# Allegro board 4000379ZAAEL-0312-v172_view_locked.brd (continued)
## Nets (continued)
GND: C1.2 C2.2 C9.2 C10.2 C11.2 C12.2 C13.2 C14.2 C15.2 C16.2 C18.2 C19.2 C20.2 C21.2 C22.2 C23.2 C24.2 C25.2 C26.2 C27.2 C28.2 C29.2 C94.2 C95.2 C96.2 C98.2 C99.2 C100.2 C101.2 C102.2 C103.2 C104.2 C105.2 C106.2 C110.2 C111.2 C112.2 C113.2 C114.2 C115.2 C116.2 C117.2 C136.2 C137.2 C139.2 C140.2 C141.2 C142.2 C143.2 C144.2 C145.2 C146.2 C148.2 C151.2 C153.2 C154.2 C155.2 C156.2 C159.2 C160.2 C161.2 C162.2 C166.1 C167.2 C168.2 C169.2 C170.1 C171.2 C172.2 C173.2 C174.2 C175.1 C176.2 C177.2 C178.2 C179.2 C180.1 C181.2 C182.1 C183.2 C184.2 C185.2 C186.2 C187.1 C188.2 C189.2 C190.2 C191.2 C192.2 C193.1 C194.2 C195.2 C196.2 C197.2 C198.2 C199.2 C200.2 C201.2 C202.2 C203.2 C204.2 C205.2 C206.2 C207.2 C208.1 C209.2 C210.2 C211.1 C212.2 C213.1 C214.1 C215.2 C216.1 C217.1 C218.2 C219.2 C220.1 C221.1 C222.2 C223.2 C224.1 C225.1 C226.2 C227.2 C228.1 C229.1 C230.2 C231.2 C232.2 C233.2 C235.2 C236.2 C238.2 C239.2 C241.2 C259.2 C260.2 C261.2 C262.2 C263.1 C264.2 C265.2 C266.2 C267.2 C272.2 C276.2 C277.2 C278.2 C279.2 C280.2 C281.2 C282.2 C283.2 C284.2 C285.2 C286.2 C293.2 C602.2 C603.2 C606.2 C607.2 C608.2 C611.2 C612.1 C613.2 C614.2 C616.2 C619.2 C620.2 C623.2 C624.2 C625.2 C626.2 C631.2 C632.2 C633.2 C634.2 C635.2 C636.2 C637.2 C638.2 C639.2 C640.2 C643.2 C644.2 C719.2 C810.2 C911.2 C922.2 C925.2 C926.2 C927.2 C928.2 C944.2 C946.2 C947.2 C948.2 C949.2 C956.2 C957.2 C958.2 C959.2 C960.2 C961.2 C971.2 C972.2 C973.2 C974.2 C976.2 C977.2 C978.2 C979.2 C980.2 C981.1 C1002.2 C1003.2 C1004.2 C1005.2 C1007.2 C1008.2 C1009.2 C1010.2 C1011.2 C1012.2 C1013.2 C1014.2 C8559.2 C8561.2 C8562.2 C8564.2 C8565.2 C8566.2 C8567.2 C8568.2 C8585.2 C8586.2 CE19.2 CE20.2 CE21.2 CE22.2 CE23.2 CE24.2 CE25.2 CE26.2 CE27.2 CE28.2 CE29.2 CE30.2 CE31.2 CE32.2 CE33.2 CE34.2 CE35.2 CE36.2 CE37.2 CE38.2 CE72.2 CE73.2 CE74.2 CE75.2 CE76.2 CE77.2 CE78.2 CE79.2 CE80.2 CE81.2 D65.1 D66.1 D67.1 D68.1 D69.1 D70.1 D71.1 D72.1 D77.1 D78.1 D87.1 D88.1 D93.1 D94.1 D95.1 D96.1 D601.C D903.2 D904.2 E1C1.2 E1C2.2 E1C14.2 E1C16.2 E1C21.2 E1C22.2 E1C23.2 E1C24.2 E1C29.2 E1C30.2 E1C31.2 E1C32.1 E1C33.2 E1C34.2 E1C35.2 E1C36.2 E1C37.1 E1C38.1 E1C39.2 E1C40.2 E1C41.2 E1C42.1 E1C43.1 E1C44.1 E1C45.2 E1C46.2 E1C47.1 E1C48.1 E1C49.1 E1C50.1 E1C51.1 E1C52.1 E1C53.1 E1C54.1 E1C55.1 E1C56.1 E1C57.1 E1C58.1 E1C59.2 E1C60.2 E1C61.1 E1C62.1 E1C63.1 E1C64.2 E1C65.1 E1C66.1 E1C67.1 E1C68.1 E1C69.1 E1C70.2 E1C71.2 E1C72.2 E1C73.2 E1C74.1 E1C75.1 E1C76.2 E1C77.1 E1C78.1 E1C79.1 E1C80.1 E1C81.2 E1C82.1 E1C83.2 E1C84.1 E1C85.1 E1C86.1 E1C87.2 E1C88.2 E1C89.1 E1C90.1 E1C91.2 E1C92.2 E1C93.2 E1C94.2 E1C95.1 E1C96.2 E1C97.2 E1C98.2 E1C99.1 E1C100.2 E1C149.2 E1C150.2 E1C151.2 E1C152.2 E1R5.1 E1R12.2 E1R13.2 E1R14.1 E1R15.1 E1R20.2 E1R26.1 E1R27.2 E1R28.2 E1R29.2 E1R30.2 E1R31.2 E1U1.4 E1U1.9 E1U1.12 E1U1.15 E1U1.18 E1U1.43 E1U1.47 E1U1.51(SGND_3) E1U1.60 E1U1.67 E1U1.69 E1U1.70 E1U1.71 E1U1.72 E1U1.73 E1U1.74 E1U1.75 E1U1.76 E1U1.77 E1U1.78 E1U1.79 E1U1.80 E1U1.81 E1U1.82 E1U1.83 E1U1.84 E1U1.85 E1U1.86 E1U1.87 E1U1.88 E1U1.89 E1U1.90 E1U1.91 E1U1.92 E1U1.93 E1U1.94 E1U1.95 E1U1.96 E1U1.97 E1U1.98 E1U1.99 E1U1.100 E1U1.101 E1U1.102 E1U1.103 E1U1.104 E1U1.105 E1U1.106 E1U1.107 E1U1.108 E1U1.109 E1U1.110 E1U1.111 E1U1.112 E1U1.113 E1U1.114 E1U1.115 E1U1.116 E1U1.117 E1U1.118 E1U1.119 E1U1.120 E1U1.121 E1U1.122 E1U1.123 E1U1.124 E1U1.125 E1U1.126 E1U1.127 E1U1.128 E1U1.129 E1U1.130 E1U1.131 E1U1.132 E1U1.133 E1U1.134 E1U1.135 E1U1.136 E1U1.137 E1U1.138 E1U1.139 E1U1.140 E1U1.141 E1U1.142 EC16.2 EC17.2 EC18.2 EC19.2 EC20.2 EC21.2 EC22.2 EC300.1 EC301.1 EC340.1 EY300.2 EY300.4(GND2) H01.1 H02.1 H03.1 H04.1 J1.5 J7.4 PC351.2 PC352.2 PC353.2 PC354.2 PC355.2 PC358.2 PC359.2 PC360.2 PC361.2 PC362.2 PC363.2 PC366.2 PC367.2 PC368.2 PC369.2 PC370.2 PC371.2 PC372.2 PC373.2 PC374.2 PC375.2 PC376.2 PC377.2 PC379.2 PC380.2 PC381.2 PC385.2 PC386.2 PC387.2 PC388.2 PC389.2 PC390.2 PC391.2 PC392.2 PC393.2 PC394.2 PC395.2 PC396.2 PC399.2 PC400.2 PC401.2 PC402.2 PC403.2 PC404.2 PC405.2 PC406.2 PC407.2 PC430.2 PC484.2 PC485.2 PC486.2 PC487.2 PC677.2 PC679.2 PC680.2 PC681.2 PC682.2 PC684.2 PC685.2 PC686.2 PC687.2 PC688.2 PC689.2 PC690.2 PR337.2 PR338.2 PR342.2 PR352.2 PR353.2 PR354.2 PR461.2 PR465.2 PR468.2 PR471.2 PR607.2 PR609.2 PU10.2 PU10.3 PU10.4 PU10.9 PU14.4 PU15.4 PU16.4 PU17.4 PU23.1 PU40.2 PU40.3 PU40.4 PU40.9 PU902.2 PU908.2 Q1.E Q2.E Q3.E Q4.E Q5.E Q6.E Q7.E Q8.E Q9.E Q10.E Q600.S(SOURCE) R28.1 R131.1 R132.1 R135.2 R136.2 R151.1 R154.2 R156.2 R174.2 R182.2 R184.2 R186.2 R188.2 R190.2 R192.2 R194.2 R199.1 R254.1 R255.1 R256.1 R257.1 R274.1 R278.2 R613.2 R621.2 R641.2 R642.1 R644.1 R647.2 R652.2 R664.2 R905.2 R916.2 R928.2 R936.2 R937.2 R939.2 R940.2 R941.2 R976.2 R978.2 R980.2 R983.2 R992.1 R993.1 R994.1 R1000.1 R1007.2 R1009.2 R1013.2 SC129.2 SC130.2 SC131.2 SC133.2 SC134.2 SC135.2 SC136.2 SC138.2 SC141.2 SC147.2 SC148.2 SC149.2 SC150.2 SC151.2 SC152.2 SC153.2 SC157.2 SC158.1 SC163.1 SC164.2 SC165.2 SC168.2 SC214.2 SC215.2 SC216.2 SC218.2 SC219.2 SC235.1 SC236.1 SC239.1 SC240.1 SC242.2 SC246.1 SC247.1 SC248.1 SC249.1 SC250.2 SC251.2 SC252.2 SC253.1 SC254.2 SC256.2 SC264.2 SC265.2 SC266.2 SC267.1 SC268.1 SC269.2 SC273.1 SC274.1 SC275.1 SC435.1 SC446.2 SC447.2 SC448.2 SC449.2 SC465.2 SC466.2 SC467.2 SC469.2 SC470.2 SC472.2 SC473.2 SC474.2 SC475.2 SC476.2 SC477.2 SC478.2 SC479.2 SC484.2 SC485.2 SC486.2 SC488.2 SC489.2 SC490.2 SC492.2 SC493.2 SC494.2 SC495.2 SC496.2 SC499.2 SC500.2 SC501.2 SC502.2 SC504.2 SC506.2 SC509.2 SC510.2 SC512.2 SC513.2 SC514.2 SC515.2 SC517.2 SC518.2 SC519.2 SC520.2 SC521.2 SC523.2 SC600.1 SC601.1 SC602.1 SF600.1 SF600.2 SF600.3 SF601.1 SF601.2 SF602.1 SF602.2 SF602.3 SF602.4 SF603.1 SF603.2 SF603.3 SF604.1 SF604.2 SF604.3 SR40.1 SR42.1 SR50.1 SR72.2 SR74.1 SR75.1 SR79.1 SR87.2 SR89.1 SR91.1 SR93.1 SR94.1 SR119.1 SR124.1 SR129.1 SR132.1 SR133.1 SR390.2 SR485.2 SR536.2 SW800.2 SW800.3 SW800.4(GND2) SY3.2 SY3.4(GND_2) T5.6 TP30.1 U1.A2 U1.A15 U1.A28 U1.AA4 U1.AA6 U1.AA10 U1.AA16 U1.AA18 U1.AB1 U1.AC6 U1.AC12 U1.AC20 U1.AC22 U1.AC25 U1.AD1 U1.AE10 U1.AE14 U1.AE16 U1.AE22 U1.AE24 U1.AF5 U1.AG1 U1.AG7 U1.AG29 U1.AH2 U1.AH11 U1.AH13 U1.AH15 U1.AH17 U1.AH21 U1.AH28 U1.B1 U1.B29 U1.C6 U1.C25 U1.D14 U1.D24 U1.E4 U1.E26 U1.F6 U1.F16 U1.F18 U1.F25 U1.H3 U1.H8 U1.H16 U1.H24 U1.H27 U1.K10 U1.K14 U1.K18 U1.K22 U1.K29 U1.M1 U1.M12 U1.M16 U1.M20 U1.M25 U1.P8 U1.P12 U1.P20 U1.P24 U1.P29 U1.R26 U1.T8 U1.T14 U1.T16 U1.T18 U1.U10 U1.U12 U1.U16 U1.U22 U1.U25 U1.U26(VSSA_XO1) U1.V1 U1.W4 U1.W8 U1.W14 U1.W18 U1.W24 U1.Y1 U5.1 U5.2 U5.3 U5.4 U7.4 U12.A9 U12.B1 U12.B3 U12.B9 U12.D1 U12.D8 U12.E1 U12.E2 U12.E8 U12.F9 U12.G1 U12.G8 U12.G9 U12.J2 U12.J8 U12.M1 U12.M9 U12.P1 U12.P9 U12.T1 U12.T9 U13.A9 U13.B1 U13.B3 U13.B9 U13.D1 U13.D8 U13.E1 U13.E2 U13.E8 U13.F9 U13.G1 U13.G8 U13.G9 U13.J2 U13.J8 U13.M1 U13.M9 U13.P1 U13.P9 U13.T1 U13.T9 U18.4 U18.9 U18.10 U18.11 U18.12 U18.13 U18.14 U18.15 U18.16 U18.17 U18.18 U18.19 U18.20 U18.21 U18.22 U18.23 U18.24 U18.25 U18.26 U18.27 U18.28 U18.29 U18.30 U18.31 U18.32 U18.33 U18.34 U18.35 U18.36 U18.37 U18.38 U18.39 U22.4 U39.3 U66.145 U108.GND U601.1 U601.12 U601.15(VSS_TX_2) U601.17 U601.30 U601.33 U601.34 U601.35 U601.36 U601.37 U601.38 U601.39 U601.40 U602.1 U602.3 U602.6 U602.8 U602.10 U602.13 U602.14 U602.15 U602.16 U602.17 U604.1 U604.2 U604.3 U604.4 U904.4 U904.8 U904.11 U904.12 U904.13 Y3.2 Y3.4(GND_2)
PGND: C255.2 C260.1 C261.1 C262.1 C263.2 C264.1 C265.1 C266.1 C267.1 C720.1 C844.2 C845.2 C846.2 C848.2 C849.2 C850.2 C851.2 C852.2 C8569.2 C8571.2 C8572.1 C8573.2 C8581.2 C8583.2 C8584.2 D812.A D817.A D818.A D819.A D820.A D821.A PU30.7 PU30.9 PU30.10 PU30.11 PU30.12 PU30.13 PU30.14 PU30.15 R499.2 R500.2 R501.2 R502.2 R1019.2 R1020.1 R1025.1 R1026.2 R1041.2 R1042.1 R1043.2 R1044.1 R1047.2 RV1.A T5.11 T5.12 U22.5 U909.7 U909.11 U909.18 U909.22 U909.23
SVDD0_CK: E1C97.1 E1C98.1 E1C99.2 E1L5.2 E1U1.50
SVDD0_TRX: E1C93.1 E1C94.1 E1C95.2 E1L6.2 E1U1.46
VCC_0V6_DDR: C143.1 C144.1 C145.1 C146.1 C976.1 C977.1 C978.1 C979.1 C980.1 R105.1 R106.1 R107.1 R108.1 R109.1 R110.1 R111.1 R112.1 R113.1 R114.1 R115.1 R116.1 R118.1 R119.1 R120.1 R121.1 R122.1 R123.1 R124.1 R125.1 R126.1 R127.1 R128.1 R130.1 R918.2 R951.1 R1036.1
VCC_0V9_PRX321: C9.1 C10.1 C11.1 C12.1 C14.1 C15.1 C167.1 C174.1 C179.1 C183.1 C208.2 C209.1 C211.2 C212.1 C214.2 C215.1 C217.2 C218.1 C221.2 C222.1 C225.2 C226.1 C229.2 C230.1 FB7.1 FB8.1 PR387.1 PR388.1 R916.1 U1.M14 U1.M18 U1.P14 U1.P16 U1.P18 U1.T12 U1.T20 U1.T22 U1.U14 U1.U18 U1.U20 U1.W12 U1.W20 U1.W22
VCC_0V9_PRX321_XFI: C2.1 C189.1 C198.1 C202.1 C206.1 C207.1 FB8.2 U1.AA24 U1.AC18 U1.T10 U1.W10
VCC_1V0_8261BE: E1C2.1 E1C29.1 E1C30.1 E1C31.1 E1C32.2 E1C33.1 E1C34.1 E1C35.1 E1C36.1 E1C37.2 E1C38.2 E1C50.2 E1C51.2 E1C52.2 E1C53.2 E1C54.2 E1C55.2 E1C56.2 E1C57.2 E1C58.2 E1C66.2 E1C67.2 E1C79.2 E1C80.2 E1C96.1 E1C100.1 E1L3.1 E1L4.1 E1L5.1 E1L6.1 E1U1.26 E1U1.32 E1U1.42 E1U1.53 E1U1.57 R937.1 RP1126.1
VCC_1V8_PRX321: C16.1 C18.1 C21.1 C22.1 C23.1 C25.1 C26.1 C27.1 C922.1 C926.1 C927.1 C1004.1 C1005.1 C1006.1 FB5.1 FB6.1 FB10.1 FB12.1 FB13.1 FB15.1 PR113.1 PU902.5(VOUT) R172.1 R928.1 R984.1
VCC_1V8_PRX321_PLL: C19.1 C20.1 C1009.1 C1010.1 C1012.1 FB14.1 PU908.5(VOUT) R980.1
VCC_1V9_8261BE: E1C23.1 E1C24.1 E1C48.2 E1C49.2 E1C68.2 E1C69.2 E1C70.1 E1C71.1 E1C72.1 E1C73.1 E1C74.2 E1C75.2 E1C84.2 E1C85.2 E1FB1.1 E1L2.1 E1LP1.1 E1R3.1 E1R24.1 E1R25.1 E1U1.24 E1U1.33 E1U1.36 E1U1.55 R939.1 RP1128.1
VCC_1V35_DDR: C94.1 C95.1 C96.1 C99.1 C100.1 C102.1 C103.1 C104.1 C105.1 C106.1 C110.1 C112.1 C113.1 C114.1 C115.1 C116.1 C140.1 C141.1 C142.1 C159.1 C168.1 C169.1 C171.1 C172.1 C176.1 C177.1 C184.1 C185.1 C190.1 C191.1 C195.1 C196.1 C200.1 C201.1 C204.1 C205.1 C232.1 C928.1 C958.1 C959.1 C960.1 C961.1 C971.1 C972.1 C973.1 C974.1 R936.1 R938.1 R1035.1 RP1124.1 U1.H6 U1.H10 U1.H12 U1.H20 U1.H22 U1.H25 U1.K8 U1.K12 U1.K16 U1.K20 U1.K24 U1.M8 U1.M24 U12.A1 U12.A8 U12.B2 U12.C1 U12.C9 U12.D2 U12.D9 U12.E9 U12.F1 U12.G7 U12.H2 U12.H9 U12.K2 U12.K8 U12.N1 U12.N9 U12.R1 U12.R9 U13.A1 U13.A8 U13.B2 U13.C1 U13.C9 U13.D2 U13.D9 U13.E9 U13.F1 U13.G7 U13.H2 U13.H9 U13.K2 U13.K8 U13.N1 U13.N9 U13.R1 U13.R9
VCC_3V3_8261BE: E1C86.2 E1C87.1 E1C88.1 E1C89.2 E1C90.2 E1C91.1 E1C92.1 E1U1.22 E1U1.31 ER331.1 RP1132.2
VCC_3V3_PON: C173.1 C178.1 C186.1 C192.1 C197.1 C199.1 C203.1 C277.1 C278.1 C616.1 C631.1 C632.1 C633.1 C634.1 C635.1 C636.1 C719.1 C911.1 C1003.1 C1008.1 CE72.1 CE73.1 CE74.1 CE75.1 CE76.1 CE77.1 CE78.1 CE79.1 CE80.1 CE81.1 D802.A D803.A D804.A D805.A D806.A D810.A D822.A D823.A D824.A D825.A FB9.1 L606.1 L607.1 L611.1 L612.1 PR383.2 PR462.2 PR464.2 PR467.2 PR470.2 PR610.2 PR612.1 PR614.1 PR619.1 PU902.1 PU908.1 R68.2 R83.2 R89.2 R93.2 R94.2 R152.1 R155.1 R181.1 R183.1 R185.1 R187.1 R191.1 R193.1 R203.1 R229.1 R230.1 R231.1 R232.1 R233.1 R234.1 R235.1 R258.1 R277.1 R350.2 R351.2 R629.2 R630.2 R809.2 R830.1 R831.1 R832.1 R833.1 R834.1 R835.1 R836.1 R837.1 R838.1 R839.1 R905.1 R949.1 R956.1 R958.1 R977.1 R979.1 R1034.1 RP1131.1 RP1132.1 U1.AA25 U1.P6 U1.U24 U1.W16 U1.W25 U18.8 U22.1 U604.8
VCC_3V3_PRX321_GPHY: C13.1 C166.2 C170.2 C175.2 C182.2 FB9.2 U1.AA20 U1.AA22 U1.AC24
VCC_3V3_PSE: C720.2 C8572.2 D3.C R91.1 R352.2 R353.2 R495.2 U22.8(VCC2) U909.1 U909.24
VCC_20V0_SYS: C17.1 C8564.1 C8565.1 C8567.1 C8585.1 C8586.1 PR386.1 PR611.1 PU23.8(VIN) R66.1 R1008.1 R1015.1 R1016.1 R1029.1 R1030.1 R1031.1 RP1123.1 RP1125.1 RP1127.1 RP1129.1 T5.3 T5.4
VCC_20V0_USB_PD: C8560.1 C8562.1 Q802.5 Q802.6 Q802.7 Q802.8 R999.1 U27.13 USB1.A4 USB1.A9 USB1.B4 USB1.B9(VBUS4)
VDD_DIG: C611.1 C625.1 C626.1 L607.2 U601.4
VDD_RX: C606.1 C623.1 C624.1 L604.1 L606.2 R605.1 U601.32
VDD_RX2: C638.1 C639.1 L605.1 L611.2
VDD_TX: C608.1 C637.1 C640.1 C643.1 C644.1 L612.2 R604.1 R606.1 R610.1 R699.1 U601.19 U601.22
1G_TCT_A: C156.1 D69.2 T2.1
1G_TCT_B: C276.1 D72.2 T2.4
1G_TCT_C: C139.1 D70.2 T2.7
1G_TCT_D: C160.1 D71.2 T2.10
1GLAN_BIDA+: P5.1 RV59.2 T2.23
1GLAN_BIDA-: P5.2 RV59.1 T2.22
1GLAN_BIDB+: P5.3 RV58.2 T2.20
1GLAN_BIDB-: P5.6 RV58.1 T2.19
1GLAN_BIDC+: P5.4 RV57.2 T2.17
1GLAN_BIDC-: P5.5 RV57.1 T2.16
1GLAN_BIDD+: P5.7 RV56.2 T2.14
1GLAN_BIDD-: P5.8 RV56.1 T2.13
1GLAN_MCT_C: C247.1 D83.1 D116.2 T2.18
1GLAN_MCT_D: C246.1 D85.1 D115.2 T2.15
2G5_TCT_A0: C280.1 D77.2 T17.1
2G5_TCT_A1: C284.1 D93.2 T17.13
2G5_TCT_B0: C282.1 D88.2 T17.4
2G5_TCT_B1: C286.1 D96.2 T17.16
2G5_TCT_C0: C279.1 D78.2 T17.7
2G5_TCT_C1: C283.1 D94.2 T17.19
2G5_TCT_D0: C281.1 D87.2 T17.10
2G5_TCT_D1: C285.1 D95.2 T17.22
2G5LAN_BIDA0+: P6.1 RV63.2 T17.47
2G5LAN_BIDA0-: P6.2 RV63.1 T17.46
2G5LAN_BIDA1+: P4.1 RV67.2 T17.35
2G5LAN_BIDA1-: P4.2 RV67.1 T17.34
2G5LAN_BIDB0+: P6.3 RV62.2 T17.44
2G5LAN_BIDB0-: P6.6 RV62.1 T17.43
2G5LAN_BIDB1+: P4.3 RV65.2 T17.32
2G5LAN_BIDB1-: P4.6 RV65.1 T17.31
2G5LAN_BIDC0+: P6.4 RV61.2 T17.41
2G5LAN_BIDC0-: P6.5 RV61.1 T17.40
2G5LAN_BIDC1+: P4.4 RV66.2 T17.29
2G5LAN_BIDC1-: P4.5 RV66.1 T17.28
2G5LAN_BIDD0+: P6.7 RV60.2 T17.38
2G5LAN_BIDD0-: P6.8 RV60.1 T17.37
2G5LAN_BIDD1+: P4.7 RV64.2 T17.26
2G5LAN_BIDD1-: P4.8 RV64.1 T17.25
2G5LAN_MCT_C0: C256.1 D105.1 D124.2 T17.42
2G5LAN_MCT_C1: C251.1 D101.1 D120.2 T17.30
2G5LAN_MCT_D0: C254.1 D107.1 D123.2 T17.39
2G5LAN_MCT_D1: C250.1 D103.1 D119.2 T17.27
10GLAN_BIDA+: P3.1 RV55.2 T1.23
10GLAN_BIDA-: P3.2 RV55.1 T1.22
10GLAN_BIDB+: P3.3 RV54.2 T1.20
10GLAN_BIDB-: P3.6 RV54.1 T1.19
10GLAN_BIDC+: P3.4 RV53.2 T1.17
10GLAN_BIDC-: P3.5 RV53.1 T1.16
10GLAN_BIDD+: P3.7 RV52.2 T1.14
10GLAN_BIDD-: P3.8 RV52.1 T1.13
10GLAN_MCT_C: C243.1 D79.1 D112.2 T1.18
10GLAN_MCT_D: C242.1 D81.1 D111.2 T1.15
10GPHY_MDI_BIDA_N: E1U1.16 RV42.1 T1.3
10GPHY_MDI_BIDA_P: E1U1.17 RV42.2 T1.2
10GPHY_MDI_BIDB_N: E1U1.11 RV41.1 T1.6
10GPHY_MDI_BIDB_P: E1U1.10 RV41.2 T1.5
10GPHY_MDI_BIDC_N: E1U1.5 RV40.1 T1.9
10GPHY_MDI_BIDC_P: E1U1.6 RV40.2 T1.8
10GPHY_MDI_BIDD_N: E1U1.3 RV39.1 T1.12(TD4-)
10GPHY_MDI_BIDD_P: E1U1.2 RV39.2 T1.11
10GPHY_TCT_A: C136.1 C137.1 C148.1 C151.1 D65.2 D66.2 D67.2 D68.2 E1C14.1 E1C16.1 E1C149.1 E1C150.1 E1C151.1 E1C152.1 E1L1.2 T1.1 T1.4 T1.7 T1.10
APD_BIAS: C612.2 R662.2 R665.2 U602.2
APD_FB: R648.2 R651.2 R664.1 U601.8
APD_PWM: Q600.G R617.1 R647.1
BS_CLK_SEL: E1R26.2 E1U1.52
BS_MDI_ORDER: E1R24.2 E1U1.35
BS_PHY_DIS: E1R25.2 E1U1.34
BS_PHYAD0: E1R27.1 E1U1.41
BS_PHYAD1: E1R28.1 E1U1.40
BS_PHYAD2: E1R29.1 E1U1.39
BS_PHYAD3: E1R30.1 E1U1.38
BS_PHYAD4: E1R31.1 E1U1.37
CC1: D128.2 R1039.2 USB1.A5
CC2: D127.2 R1040.2 USB1.B5
CLK_XTALI_50MHZ_RTL8261BE: E1R1.1 EC300.2 EY300.3
CLK_XTALO_50MHZ_RTL8261BE: E1R2.1 EC301.2 EY300.1
COMP: PU23.3 U39.4
CS+: C8558.1 R992.2 U27.7
D+: D110.2 R357.2 USB1.A6 USB1.B6
D-: D109.2 R358.2 USB1.A7 USB1.B7
DDR_A0: R105.2 U1.C23 U12.N3 U13.N3
DDR_A1: R106.2 U1.B22 U12.P7 U13.P7
DDR_A2: R107.2 U1.D22 U12.P3 U13.P3
DDR_A3: R108.2 U1.A21 U12.N2 U13.N2
DDR_A4: R109.2 U1.C21 U12.P8 U13.P8
DDR_A5: R110.2 U1.B20 U12.P2 U13.P2
DDR_A6: R111.2 U1.D20 U12.R8 U13.R8
DDR_A7: R112.2 U1.A19 U12.R2 U13.R2
DDR_A8: R113.2 U1.C19 U12.T8 U13.T8
DDR_A9: R114.2 U1.B18 U12.R3 U13.R3
DDR_A10: R115.2 U1.D18 U12.L7 U13.L7
DDR_A11: R116.2 U1.A17 U12.R7 U13.R7
DDR_A12: R118.2 U1.C17 U12.N7 U13.N7
DDR_A13: R119.2 U1.B16 U12.T3 U13.T3
DDR_A14: R120.2 U1.A11 U12.T7 U13.T7
DDR_A15: R121.2 U1.A23 U12.M7 U13.M7
DDR_ALERT: R132.2 U1.F12
DDR_BA_0: R123.2 U1.B12 U12.M2 U13.M2
DDR_BA_1: R124.2 U1.D12 U12.N8 U13.N8
DDR_BA_2/BG_0: R125.2 U1.C11 U12.M3 U13.M3
DDR_BL0_DQ0: U1.G2 U12.F2
DDR_BL0_DQ1: U1.B4 U12.F7
DDR_BL0_DQ2: U1.F3 U12.G2
DDR_BL0_DQ3: U1.A4 U12.H8
DDR_BL0_DQ4: U1.G4 U12.E3
DDR_BL0_DQ5: U1.A6 U12.F8
DDR_BL0_DQ6: U1.F1 U12.H3
DDR_BL0_DQ7: U1.D5 U12.H7
DDR_BL0_LDM: U1.C3 U12.E7
DDR_BL0_LDQS_N: U1.D2 U12.G3
DDR_BL0_LDQS_P: U1.D1 U12.F3
DDR_BL1_DQ8: U1.J2 U12.C2
DDR_BL1_DQ9: U1.N4 U12.C8
DDR_BL1_DQ10: U1.K3 U12.A3
DDR_BL1_DQ11: U1.L2 U12.D7
DDR_BL1_DQ12: U1.J4 U12.C3
DDR_BL1_DQ13: U1.P1 U12.B8
DDR_BL1_DQ14: U1.K1 U12.A2
DDR_BL1_DQ15: U1.L4 U12.A7
DDR_BL1_UDM: U1.H1 U12.D3
DDR_BL1_UDQS_N: U1.N2 U12.B7
DDR_BL1_UDQS_P: U1.M3 U12.C7
DDR_BL2_DQ16: U1.A25 U13.E3
DDR_BL2_DQ17: U1.C28 U13.F7
DDR_BL2_DQ18: U1.B26 U13.F2
DDR_BL2_DQ19: U1.F27 U13.H8
DDR_BL2_DQ20: U1.D25 U13.H3
DDR_BL2_DQ21: U1.G26 U13.F8
DDR_BL2_DQ22: U1.A26 U13.G2
DDR_BL2_DQ23: U1.F29 U13.H7
DDR_BL2_LDM: U1.G28 U13.E7
DDR_BL2_LDQS_N: U1.D29 U13.G3
DDR_BL2_LDQS_P: U1.D28 U13.F3
DDR_BL3_DQ24: U1.N28 U13.C2
DDR_BL3_DQ25: U1.J28 U13.A7
DDR_BL3_DQ26: U1.N26 U13.A3
DDR_BL3_DQ27: U1.K27 U13.B8
DDR_BL3_DQ28: U1.P27 U13.C3
DDR_BL3_DQ29: U1.J26 U13.D7
DDR_BL3_DQ30: U1.M29 U13.A2
DDR_BL3_DQ31: U1.H29 U13.C8
DDR_BL3_UDM: U1.M27 U13.D3
DDR_BL3_UDQS_N: U1.L26 U13.B7
DDR_BL3_UDQS_P: U1.L28 U13.C7
DDR_CAS_N: R127.2 U1.A13 U12.K3 U13.K3
DDR_CK_N: R133.1 U1.B14 U12.K7 U13.K7
DDR_CK_P: R133.2 U1.C15 U12.J7 U13.J7
DDR_CKE_0: R126.2 U1.B7 U12.K9 U13.K9
DDR_CS_0: R130.2 U1.B10 U12.L2 U13.L2
DDR_ODT_0: R128.2 U1.A9 U12.K1 U13.K1
DDR_PAR: R131.2 U1.F14
DDR_RAS_N: R122.2 U1.C13 U12.J3 U13.J3
DDR_RST: C24.1 U1.B24 U12.T2 U13.T2
DDR_WE_N: R951.2 U1.D16 U12.L3(\\W\E) U13.L3(\\W\E)
DDR_ZQ_0: R135.1 U12.L8
DDR_ZQ_1: R136.1 U13.L8
DUT_AVDDHC_3V3: EC16.1 EC17.1 EC18.1 EC19.1 EC20.1 EC21.1 EC22.1 J1.1(VCC) RP1131.2 SC129.1 SC130.1 SC131.1 SC138.1 SC147.1 SC149.1 SC150.1 SC157.1 SC242.1 SC264.1 SC269.1 SC448.1 SC484.1 SC485.1 SC488.1 SC489.1 SC494.1 SC495.1 SC496.1 SC504.1 SC509.1 SC510.1 SC518.1 SC519.1 SD2.C SR39.2 SR41.2 SR43.2 SR49.2 SR51.2 SR56.2 SR57.1 SR58.2 SR62.1 SR63.1 SR64.2 SR65.2 SR67.2 SR71.2 SR73.1 SR76.2 SR80.1 SR81.1 SR82.1 SR84.1 SR85.1 SR88.1 SR90.1 SR96.2 SR98.1 SR127.2 SR153.1 SR157.1 SR611.1 SR612.1 SR613.1 SR614.1 TP25.1 U5.8 U7.8 U66.7 U66.17 U66.41 U66.49 U66.61 U66.69 U66.91 U66.97 U66.106 U66.127 U66.139 U108.VCC
DUT_AVDDL_1GXG_0V95: SC218.1 SC219.1 SL17.2 U66.54
DUT_AVDDLC_0V95: R940.1 RP1130.1 SC133.1 SC148.1 SC151.1 SC152.1 SC153.1 SC214.1 SC215.1 SC216.1 SC446.1 SC447.1 SC449.1 SC465.1 SC466.1 SC467.1 SC469.1 SC470.1 SC472.1 SC473.1 SC474.1 SC475.1 SC476.1 SC477.1 SC478.1 SC479.1 SC486.1 SC490.1 SC492.1 SC493.1 SC506.1 SC512.1 SC513.1 SC514.1 SC515.1 SC517.1 SL17.1 SL29.1 U66.1 U66.2 U66.3 U66.5 U66.19 U66.21 U66.29 U66.31 U66.32 U66.39 U66.48 U66.62 U66.71 U66.78 U66.79 U66.81 U66.87 U66.89 U66.99 U66.100 U66.101 U66.105 U66.114 U66.121 U66.125 U66.126 U66.141 U66.143
DUT_SVDDLCMU_0V95: SC134.1 SC135.1 SC136.1 SC141.1 SL29.2 U66.111 U66.118
EAR_GND: C233.1 C234.2 C237.2 C238.1 C241.1 C259.1 C288.2 C293.1 C294.2 D79.2 D80.2 D81.2 D82.2 D83.2 D84.2 D85.2 D86.2 D101.2 D102.2 D103.2 D104.2 D105.2 D106.2 D107.2 D108.2 D111.1 D112.1 D113.1 D114.1 D115.1 D116.1 D117.1 D118.1 D119.1 D120.1 D121.1 D122.1 D123.1 D124.1 D125.1 D126.1 P3.G1 P3.G2 P4.G1 P4.G2 P5.G1 P5.G2 P6.G1 P6.G2
EE_M_SCL: SR64.1 SR69.1 U5.6
EE_M_SDA: SR67.1 SR70.1 U5.5
EE_SCL: R639.2 R642.2 U601.25
EE_SDA: R633.2 R644.2 U601.24
ETH1_MDC: SR138.2 U66.96
ETH1_MDIO: SR136.2 U66.98
FXM_CLKMD: R172.2 U1.R28
FXM_DDR_ZQ: R174.1 U1.F10
FXM_FSOURCE: R278.1 U1.K25
FXM_GPIO0: R155.2 R156.1 U1.V27 U18.6
FXM_GPIO1: R181.2 R182.1 U1.U28 U18.1
FXM_GPIO2: U1.V29 U18.5
FXM_GPIO3: U1.W26 U18.2
FXM_GPIO4: U1.W28 U18.3(WP#/IO2)
FXM_GPIO5: U1.Y27 U18.7
FXM_JRST_N: R83.1 R274.2 U1.U2
FXM_JTCK: R94.1 U1.F8
FXM_JTDI: R89.1 U1.U4
FXM_JTDO: R191.2 R192.1 U1.U6
FXM_JTMS: R93.1 U1.P3
FXM_P0_R: R151.2 U1.AG3
FXM_P2_TXN: C271.1 U1.AG14
FXM_P2_TXP: C270.1 U1.AF15
FXM_POR_N: C272.1 R68.1 R949.2 R963.2 R975.2 U1.K6
FXM_RCAL: R199.2 U1.AE26
FXM_XTAL1: R198.2 U1.T27
FXM_XTAL2: R197.2 U1.T29
GPIO13: R152.2 R190.1 U1.AC28
GPIO16: R183.2 R184.1 U1.AE29
GPIO30: SR175.1 U66.11
GPIO31: R185.2 R186.1 U1.T1
HRST_N: R200.2 R203.2 U1.M6
I2C_SCL: R229.2 R350.1 U1.AH19 U22.3 U27.3 U601.6
I2C_SDA: R230.2 R351.1 U1.AF19 U22.2 U27.2 U601.5
INT_PHY_N: E1U1.56 ER331.2 U1.AB29
LAS_N: L601.2 U601.20 U602.12
LAS_P: L603.2 U601.21 U602.11
LED00_STR_INI_MODE1: SC158.2 SR39.1 SR133.2 U66.12
LED09_STR_REG_IF_SEL_1: SC239.2 SR71.1 SR129.2 U66.23
LED15_STR_EN_PHY_R_FRC: SC246.2 SR79.2 SR96.1 U66.25
LED18_STR_EN_PHY: SC235.2 SR58.1 SR132.2 U66.30
LED21_STR_EN_SLV_MDC_DEG: SC253.2 SR40.2 SR41.1 U66.27
LED24_STR_POB_EN: SC236.2 SR119.2 SR127.1 U66.88
LED26_STR_EN_PLED: SC249.2 SR50.2 SR51.1 U66.84
LED27_STR_EE_MOD: SC435.2 SR56.1 SR124.2 U66.82
LED28_STR_SYS_LED_EN: SC240.2 SR74.2 SR76.1 U66.13
LED29: SC248.2 U66.10
LED_1G_1_G: CE38.1 R196.2 R838.2 SC275.2 TP15.1 U66.26
LED_1G_1_R: CE36.1 R195.1 R839.2 SC247.2 SR49.1 SR75.2 TP16.1 U66.28
LED_2G5_2_G: CE34.1 R189.2 R836.2 SC273.2 TP13.1 U66.22
LED_2G5_2_R: CE32.1 R180.1 R837.2 SC274.2 TP14.1 U66.24
LED_2G5_3_G: CE24.1 R179.2 R835.2 SC163.2 SR42.2 SR43.1 U66.16
LED_2G5_3_R: CE29.1 R178.1 R833.2 SC267.2 TP11.1 U66.18
LED_10G_4_G: CE19.1 E1U1.20 R173.2 R831.2 TP5.1
LED_10G_4_R: CE22.1 E1U1.19 R175.1 R830.2 TP4.1
LED_ETH_G: TP34.1 U1.AD29
LED_ETH_R: R193.2 R194.1 TP33.1 U1.AD27
LED_POWER_G: CE26.1 R176.1 R832.2 U1.AC26
LED_XPON_B: CE27.1 R177.1 R834.2 U1.AG28
LED_XPON_R: TP9.1 U1.Y29
MDC: E1U1.30 R235.2 SC265.1 SR69.2 SR607.2 U66.136
MDC_0: SR607.1 U1.AE7
MDIAN0: D92.2 T17.3 U66.34
MDIAN1: D100.2 T17.15 U66.45
MDIAN2: D76.2 T2.3 U66.58
MDIAP0: D92.1 T17.2 U66.33
MDIAP1: D100.1 T17.14 U66.44
MDIAP2: D76.1 T2.2 U66.57
MDIBN0: D91.2 T17.6 U66.36
MDIBN1: D99.2 T17.18 U66.47
MDIBN2: D75.2 T2.6 U66.60
MDIBP0: D91.1 T17.5 U66.35
MDIBP1: D99.1 T17.17 U66.46
MDIBP2: D75.1 T2.5 U66.59
MDICN0: D90.2 T17.9 U66.38
MDICN1: D98.2 T17.21 U66.51
MDICN2: D74.2 T2.9 U66.64
MDICP0: D90.1 T17.8 U66.37
MDICP1: D98.1 T17.20 U66.50
MDICP2: D74.1 T2.8 U66.63
MDIDN0: D89.2 T17.12 U66.42
MDIDN1: D97.2 T17.24(TD8-) U66.53
MDIDN2: D73.2 T2.12(TD4-) U66.66
MDIDP0: D89.1 T17.11 U66.40
MDIDP1: D97.1 T17.23 U66.52
MDIDP2: D73.1 T2.11 U66.65
MDIO: E1U1.29 R234.2 SC266.1 SR57.2 SR70.2 SR608.2 U66.134
MDIO_0: SR608.1 U1.W6
MPD: U601.16 U602.9
MSCL0_MSCK: SC502.1 SR603.2 SR611.2 U66.138
MSCL1_MOSI: SC501.1 SR604.2 SR612.2 U66.140
MSDA0_MISO: SC500.1 SR605.2 SR613.2 U66.142
MSDA1_MCSN: SC499.1 SR606.2 SR614.2 U66.144
OPT_RX_LOS: R233.2 R605.2 U1.AG20 U601.31
OPT_TX_SD: R277.2 U1.AE12 U601.23
OPT_TXFAULT: R232.2 R606.2 U1.AG12 U601.9
P4_LED2: SC268.2 TP12.1 U66.20
PON_RX_SLEEP: C602.1 R258.2 U1.AG18 U601.27
PON_TX_DIS: R231.2 R604.2 R613.1 U1.AE20 U601.10
PSE_54V0_P1+: C244.1 C248.1 C252.1 C257.1 C8573.1 C8574.1 C8575.1 C8576.1 C8577.1 D80.1 D84.1 D102.1 D106.1 D113.2 D117.2 D121.2 D125.2 D809.1 D811.1 D812.C(CATHODE) D813.1 D814.1 D820.C(CATHODE) R496.1 R1014.1 T1.21 T2.21 T17.33 T17.45 U909.28(VPWR)
PSE_54V0_P1-: C258.1 C8576.2 D108.1 D126.2 D813.2 F3.2 T17.48
PSE_54V0_P2-: C245.1 C8577.2 D82.1 D114.2 D814.2 D819.C(CATHODE) F4.2 T1.24
PSE_54V0_P3-: C249.1 C8574.2 D86.1 D118.2 D809.2 D821.C(CATHODE) F1.1 T2.24
PSE_54V0_P4-: C253.1 C8575.2 D104.1 D122.2 D811.2 F2.1 T17.36
PSE_SCL: R352.1 U22.6 U909.3
PSE_SDA: R353.1 U22.7 U909.4 U909.5
PTP_SYNC: SR390.1 U66.130
PWR_0V9_PLL5: C181.1 C188.1 C194.1 FB7.2 U1.AA12 U1.AA14
PWR_1V8_XFI0: C180.2 C235.1 FB10.2 U1.AC16
PWR_1V8_XFI1: C187.2 C236.1 FB6.2 U1.AA8
PWR_1V8_XFI2: C193.2 C239.1 FB5.2 U1.U8
PWR_DG: R28.2 R66.2 U1.P25
RESET#: SC168.1 SR128.1 SR143.2 U66.131
RESET_BUTTON_N: C810.1 C981.2 R809.1 R810.1 U1.T3
RESET_PHY_N: E1R22.1 U1.AB27
RESET_RTL8261BE_N: E1R3.2 E1R20.1 E1R22.2 E1U1.28 EC340.2
RESET_SUICIDE: R963.1 U1.AH6
RESETB: SC254.1 SD2.A SR88.2 SR90.2 SR143.1 U108.RST
RSET0: E1R5.2 E1U1.68
RSSI: Q603.3 R655.2 R660.1 R665.1
RSSI_IN: C603.1 R660.2 U601.26
RSV_TEST0: SR536.1 U66.80
RXIN1_N: C600.2 U602.4
RXIN1_P: C601.2 U602.5
RXIN_N: C601.1 U601.28
RXIN_P: C600.1 U601.29
RXOUT+: C610.2 U601.3
RXOUT-: C609.2 U601.2
RXOUTN: C609.1 U1.AF17
RXOUTP: C610.1 U1.AG16
S0RXN: SR259.1 U66.122
S0RXP: SR260.1 U66.123
S0TXN: SC85.1 U66.119
S0TXP: SC84.1 U66.120
SCL_M: R630.1 R639.1 U604.6
SDA_M: R629.1 R633.1 U604.5
SEL_XTAL: SR72.1 SR73.2 U66.103
SPF_CS#: SC256.1 SR142.2 TP24.1 U66.9
SPF_SCK: SC250.1 SR140.2 TP21.1 U66.4
SPF_SI: SC252.1 SR141.2 TP22.1 U66.6
SPF_SO: SC251.1 SR139.2 TP23.1 U66.8
SPI1_CS#: SR80.2 SR142.1 U7.1
SPI1_HOLD#: SC523.1 SR81.2 U7.7
SPI1_SCK: SR82.2 SR140.1 U7.6
SPI1_SI: SR85.2 SR141.1 U7.5
SPI1_SO: SR98.2 SR139.1 U7.2
SPI1_WP#: SR84.2 SR87.1 U7.3(WP#)
SWITCH_INT_N: U1.AA28 U66.132
SWITCH_RESET_N: SR63.2 SR128.2 U1.AA26
TX_BURST: R621.1 R623.1 R699.2 U1.AF13
TXIN_N: C271.2 U601.14
TXIN_P: C270.2 U601.13
U0RXD: SR159.1 U66.92
U0TXD: SR158.1 U66.90
UART0_RX: R955.2 R958.2 U1.R2
UART0_RX_1: D903.1 J7.3 R955.1
UART0_TX: R27.2 R187.2 R188.1 U1.R4
UART0_TX_1: D904.1 J7.2 R27.1
UPGND: C8557.2 C8558.2 C8560.2 C8595.2 C8596.2 D109.1 D110.1 D127.1 D128.1 R985.2 R993.2 R995.2 R996.2 R997.2 R998.2 U27.5 U27.6 U27.21 U27.22 U27.23 U27.24 U27.25 U27.26 U27.27 U27.28 U27.29 U27.30 USB1.25 USB1.26 USB1.27 USB1.28 USB1.29 USB1.30 USB1.A1 USB1.A12 USB1.B1 USB1.B12
USXGMII0_RD+: EC334.1 R611.1
USXGMII0_RD-: EC335.1 R612.1
USXGMII0_TD+: C86.1 ER359.1
USXGMII0_TD-: C87.1 ER360.1
USXGMII1_RD+: R615.1 SC84.2
USXGMII1_RD-: R616.1 SC85.2
USXGMII1_TD+: C89.1 SR260.2
USXGMII1_TD-: C93.1 SR259.2
USXGMII_RD+_RTL8261BE: E1U1.44 ER359.2
USXGMII_RD-_RTL8261BE: E1U1.45 ER360.2
USXGMII_TD+_RTL8261BE: E1U1.49 EC334.2
USXGMII_TD-_RTL8261BE: E1U1.48 EC335.2
VAA_1V8: C213.2 C216.2 C220.2 C224.2 C228.2 FB13.2 U1.H18 U1.M10 U1.M22 U1.T24
VAA_1V8_OTP: C1014.1 FB15.2 U1.AC8
VAA_1V8_PLL: C1.1 C210.1 C1013.1 FB14.2 U1.AC10 U1.AC14
VAA_1V8_PVT: C219.1 C223.1 C227.1 C231.1 FB12.2 U1.T6 U1.T25
VLD: C607.1 L600.1 R610.2 R614.1
VOUT: C8559.1 C8561.1 Q802.1 Q802.2 Q802.3(S_3) R1015.2 R1016.2 U27.15
VREFCA: C98.1 C101.1 C111.1 C117.1 C153.1 C154.1 C155.1 C948.1 C949.1 C956.1 C957.1 R918.1 R938.2 R941.1 R1037.1 U1.H14 U1.P10 U1.P22 U12.H1 U12.M8 U13.H1 U13.M8
XI: SR422.2 U66.104
XO: SR423.2 U66.102(XO)
XTAL_N_50M: E1R1.2 E1U1.66
XTAL_P_50M: E1R2.2 E1U1.65
N2858156: SC164.1 SR78.1 SR423.1 SY3.1
N2858168: SC165.1 SR78.2 SR422.1 SY3.3
N3905780: SR485.1 U66.55
N4210476: SR175.2 TP10.1
N4364334: SR603.1 TP26.1
N4425325: TP31.1 U66.85
N4425340: TP32.1 U66.83
N4758164: SR604.1 TP27.1
N4760323: SR605.1 TP28.1
N4760327: SR606.1 TP29.1
N17215587: C1002.1 PU902.3 R976.1 R977.2
N17224518: C1006.2 PU902.4 R983.1 R984.2
N17229070: C1007.1 PU908.3 R978.1 R979.2
N17229197: C1011.1 PU908.4
N17760544: C161.1 R198.1 Y3.1
N17761068: C162.1 R197.1 Y3.3
N17882333: R256.2 U1.AC4
N17882335: R254.2 U1.AD4
N17882341: R257.2 U1.AB3
N17882343: R255.2 U1.AC2
N17882349: R611.2 U1.AG4
N17882351: R612.2 U1.AH4
N17883614: R154.1 U1.AE18
N18711366: L602.1 R620.1 U601.18
N18711370: L602.2 L603.1 R620.2
N18711395: C619.1 C620.1 C621.1 D600.C R635.1 R636.1 R637.1 R638.1
N18711397: D600.A L605.2 Q600.D
N18711401: D601.A Q602.S(SOURCE) R652.1
N18711446: C621.2 R636.2 R648.1
N18711477: Q601.2 Q601.3 Q601.5 Q603.4(E2) R656.1
N18711479: Q601.6 Q603.1 R655.1
N18711481: Q601.4(E2) R638.2
N18711483: Q601.1 R637.2
N18711507: Q603.2 Q603.5 Q603.6 R656.2 R662.1
N18711644: L600.2 L601.1 R614.2
N18712169: Q602.G R651.1
N18712178: Q602.D R635.2
N18712277: R617.2 U601.7
N18712349: R623.2 U601.11
N18712445: C613.1 C614.1 L604.2 U602.7(VCC)
N18842601: CE20.1 Q1.B R173.1 R987.2
N18842628: D803.C R800.1
N18842711: CE21.1 Q2.B R175.2 R986.2
N18842733: Q2.C(3) R801.2 R986.1
N18842763: D810.C R801.1
N18842823: Q1.C(3) R800.2 R987.1
N18843479: CE28.1 Q5.B R177.2 R989.2
N18843504: D805.C R803.1
N18843506: Q5.C(3) R803.2 R989.1
N18851579: R810.2 SW800.1
N19004192: C28.1 C925.1 J7.1 R956.2
N19017731: CE30.1 Q6.B R178.2 R990.2
N19017798: D804.C R805.1
N19017800: Q6.C(3) R805.2 R990.1
N19057080: C249.2 R243.1
N19057084: C248.2 R242.1
N19057088: C247.2 R240.1
N19057092: C246.2 R239.1
N19057096: C234.1 R239.2 R240.2 R242.2 R243.2
N19110181: R200.1 TP1.1
N19140562: R641.1 U604.7(WP)
N19148827: PU23.5 R1007.1 R1008.2
N19149157: C947.1 R1036.2 U904.3 U904.5
N19149173: R1037.2 U904.6
N19149206: C944.1 R1034.2 U904.7 U904.9(S5) U904.10
N19149209: C8566.1 PU23.6
N19149219: C946.1 R1035.2 U904.1 U904.2
N19149443: PU23.2 R1009.1
N19149619: PU23.4 R1012.1 R1013.1
N19149820: C8568.1 PU23.9
N19149890: D807.C PU23.10 R1011.1
N19149964: D807.A Q803.G R1011.2
N19149982: Q803.S(SOURCE) R994.2 R1000.2 R1045.2
N19151513: CE25.1 Q4.B R176.2 R988.2
N19151587: D802.C R804.1
N19151589: Q4.C(3) R804.2 R988.1
N19164313: C255.1 D3.A R91.2 U909.2
N19164743: R1017.2 U909.8
N19164772: Q804.1 Q804.2 Q804.3 R1017.1 R1019.1 R1043.1
N19164775: F1.2 Q804.5 Q804.6 Q804.7 Q804.8 R1018.1
N19164778: R1018.2 U909.9
N19164928: Q804.4 U909.10
N19165359: Q805.1 Q805.2 Q805.3 R1020.2 R1021.1 R1044.2
N19165393: Q805.4 U909.14
N19165428: R1021.2 U909.12
N19165431: R1022.2 U909.13
N19165523: F2.2 Q805.5 Q805.6 Q805.7 Q805.8 R1022.1
N19176803: R1024.1 U909.16
N19176821: R1023.1 U909.15
N19177080: Q806.1 Q806.2 Q806.3 R1023.2 R1025.2 R1042.2
N19177140: F3.1 Q806.5 Q806.6 Q806.7 Q806.8 R1024.2
N19177464: Q806.4 U909.17
N19177597: Q807.1 Q807.2 Q807.3 R1026.1 R1027.2 R1041.1
N19177618: F4.1 Q807.5 Q807.6 Q807.7 Q807.8 R1028.2
N19177683: R1027.1 U909.19
N19177705: R1028.1 U909.20
N19177745: Q807.4 U909.21
N19198143: C847.1 C848.1 C849.1 C850.1 L65.2 R495.1 R498.1 R499.1
N19198187: C843.2 L65.1 PU30.6
N19198218: C844.1 C845.1 C846.1 PU30.8(VIN) R496.2 R497.1 RV1.C(CATHODE)
N19198237: C851.1 PU30.1 R497.2 R500.1
N19198257: C852.1 PU30.2
N19198264: PU30.3 R501.1
N19198365: C843.1 PU30.5
N19198416: C847.2 PU30.4 R498.2 R502.1
N19201777: D816.A Q803.D T5.1 T5.2
N19201879: D815.A T5.5
N19201900: D815.C R1012.2
N19202018: C17.2 D816.C R1029.2 R1030.2 R1031.2
N19202225: C8569.1 C8581.1 D808.C L912.1 R1032.2
N19202261: C8571.1 C8578.1 C8583.1 C8584.1 L912.2 Q808.C(3) R1014.2 R1033.1 R1046.1
N19202468: C8580.1 D808.A T5.7 T5.8
N19202480: C8580.2 R1032.1
N19203123: D817.C(CATHODE) Q808.B R1033.2
N19203481: C8578.2 D818.REF R1038.2 R1046.2 R1047.1
N19203514: Q808.E R1048.2
N19203544: R1048.1 R1049.1 U39.1
N19203613: C8582.1 D818.C R1049.2 U39.2
N19203897: C8582.2 R1038.1
N19489360: C86.2 U1.AE1
N19489361: C87.2 U1.AE2
N19489794: R615.2 U1.Y3
N19489796: R616.2 U1.AA2
N19489842: C89.2 U1.V3
N19489844: C93.2 U1.W2
N19492059: PC386.1 PC387.1 PC388.1 PC401.1 PC402.1 PR380.1 PR386.2 PU10.1(VIN(4.5V~24V))
N19492096: PC377.1 PC379.1 PC380.1 PC381.1 PC382.1 PC403.1 PL333.2 PR351.1 PR387.2 PR388.2
N19492104: PC404.1 PU10.8
N19492532: PC382.2 PR351.2 PR353.1 PU10.10
N19492579: PC383.1 PL333.1 PU10.6
N19492605: PR355.1 PU10.7
N19492617: PC383.2 PR355.2
N19494143: PC484.1 PR113.2 PR460.2 PR461.1 PU14.6
N19494174: PC351.1 PC352.1 PC355.1 PC356.1 PC367.1 PL180.2 PR339.1 RP1124.2
N19494227: PC356.2 PR337.1 PR339.2 PR344.2
N19494229: PC360.1 PC361.1 PC362.1 PR460.1 PU14.2(VIN(4.2~24V)) RP1123.2
N19494302: PC357.1 PL180.1 PU14.3
N19494349: PR345.1 PU14.5
N19494355: PC357.2 PR345.2
N19494368: PR344.1 PU14.8
N19494464: PC359.1 PU14.7
N19496414: PC679.1 PC680.1 PC688.1 PC689.1 PC690.1 PR611.2 PR615.1 PU40.1(VIN)
N19496468: PC682.1 PU40.8
N19496479: PC677.1 PR607.1 PR615.2 PU40.11
N19496629: PC683.2 PR608.2 PR609.1 PU40.10
N19496646: PC681.1 PC683.1 PC684.1 PC685.1 PC686.1 PC687.1 PL353.2 PR608.1 PR612.2 PR614.2 PR619.2
N19496749: PC691.1 PL353.1 PU40.6
N19496764: PR613.1 PU40.7
N19496772: PC691.2 PR613.2
N19531773: C8595.1 R997.1 R1040.1 U27.11
N19531775: C8596.1 R996.1 R1039.1 U27.12
N19531789: R998.1 R999.2 U27.1
N19531805: R991.2 U27.14
N19531807: Q802.4 R991.1
N19532107: C8557.1 U27.10(VDDM)
N19561994: PC353.1 PC354.1 PC363.1 PC364.1 PC368.1 PL181.2 PR340.1 RP1126.2
N19562052: PC364.2 PR338.1 PR340.2 PR347.2
N19562054: PC370.1 PC371.1 PC372.1 PR463.1 PU15.2(VIN(4.2~24V)) RP1125.2
N19562098: PC366.1 PR464.1 PU15.1
N19562127: PC365.1 PL181.1 PU15.3
N19562174: PR346.1 PU15.5
N19562180: PC365.2 PR346.2
N19562193: PR347.1 PU15.8
N19562289: PC369.1 PU15.7
N19563922: PC373.1 PC374.1 PC375.1 PC376.1 PC378.1 PL182.2 PR341.1 RP1128.2
N19563980: PC378.2 PR341.2 PR342.1 PR349.2
N19563982: PC390.1 PC391.1 PC392.1 PR466.1 PU16.2(VIN(4.2~24V)) RP1127.2
N19564055: PC384.1 PL182.1 PU16.3
N19564102: PR348.1 PU16.5
N19564108: PC384.2 PR348.2
N19564121: PR349.1 PU16.8
N19564217: PC389.1 PU16.7
N19565593: PC393.1 PC394.1 PC395.1 PC396.1 PC397.1 PL183.2 PR343.1 RP1130.2
N19565653: PC405.1 PC406.1 PC407.1 PR469.1 PU17.2(VIN(4.2~24V)) RP1129.2
N19565684: PC397.2 PR343.2 PR354.1 PR356.2
N19565697: PC399.1 PR470.1 PU17.1
N19565726: PC398.1 PL183.1 PU17.3
N19565773: PR350.1 PU17.5
N19565779: PC398.2 PR350.2
N19565792: PR356.1 PU17.8
N19565888: PC400.1 PU17.7
N19599376: C245.2 R251.1
N19599378: C244.2 R252.1
N19599380: C243.2 R253.1
N19599382: C242.2 R261.1
N19599384: C237.1 R251.2 R252.2 R253.2 R261.2
N19664892: SR65.1 U5.7(W\C\)
N19665679: J1.2 SC520.1 SR157.2 SR158.2
N19665693: J1.3 SC521.1 SR153.2 SR159.2
N19837833: C251.2 R246.1
N19837837: C252.2 R244.1
N19837859: C253.2 R245.1
N19837869: C250.2 R241.1
N19837873: C288.1 R241.2 R244.2 R245.2 R246.2
N19838616: C258.2 R248.1
N19838620: C257.2 R247.1
N19838624: C256.2 R250.1
N19838628: C254.2 R249.1
N19838632: C294.1 R247.2 R248.2 R249.2 R250.2
N19974700: E1U1.23 TP3.1
N20037364: R357.1 U27.8
N20037385: R358.1 U27.9
N20084108: SR62.2 SR609.1 TP17.1
N20170813: C29.1 PU23.7 R1045.1
N20369270: E1C1.1 E1C21.1 E1C22.1 E1L1.1 E1L2.2
N20751065: CE23.1 Q3.B R179.1 R1001.2
N20751067: Q3.C(3) R802.2 R1001.1
N20751191: D806.C R802.1
N20751626: CE33.1 Q8.B R180.2 R1003.2
N20751628: CE31.1 Q7.B R189.1 R1002.2
N20751630: Q7.C(3) R806.2 R1002.1
N20751632: Q8.C(3) R807.2 R1003.1
N20751867: D822.C R806.1
N20751906: D823.C R807.1
N20752359: CE37.1 Q10.B R195.2 R1005.2
N20752361: CE35.1 Q9.B R196.1 R1004.2
N20752363: Q9.C(3) R808.2 R1004.1
N20752365: Q10.C(3) R811.2 R1005.1
N20752600: D824.C R808.1
N20752639: D825.C R811.1
N20820874: R985.1 U27.19
N20820880: R995.1 U27.20
N20912001: SR89.2 U66.112
N20912029: SR91.2 U66.113
N20914921: SR93.2 U66.115
N20914922: SR94.2 U66.116
N24238736: E1R12.1 E1U1.58
N24238738: E1R13.1 E1U1.59
N24238740: E1R14.2 E1U1.54
N24238742: E1R15.2 E1U1.27
N24239054: E1U1.21 TP2.1
N26017682: SR610.2 U66.129
N26017689: SR609.2 U66.128
N26017934: SR610.1 TP18.1
N26023442: SR136.1 TP20.1
N26023467: SR138.1 TP19.1
N1912991617: TP8.1 U1.AE28
N1912991621: TP7.1 U1.AF21
N1912991629: TP6.1 U1.AF6

Pads without a net: E1U1 25 61 62; RV39 3 4 5 6; RV40 3 4 5 6; RV41 3 4 5 6; RV42 3 4 5 6; T5 9 10; U1 AF9 AF11 AF23 AG10 AG22 AG24 AG25 AG26 AH9 AH23 AH25 AH26 C9 D7 D10 F20 F22 F24; U12 J1 J9 L1 L9; U13 J1 J9 L1 L9; U27 4 16 17 18; U66 14 15 43 56 67 68 70 72 73 74 75 76 77 86 93 94 95 107 108 109 110 117 124 133 135 137; U909 6 25 26 27; USB1 A2 A3 A8 A10 A11 B2 B3 B8 B10 B11

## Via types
v1: diameter 0.457, hole 0.254, TOP to BOTTOM, 1185 vias
v2: diameter 0.559, hole 0.305, TOP to BOTTOM, 1325 vias
v3: diameter 0.406, hole 0.203, TOP to BOTTOM, 163 vias
v4: diameter 0.508, hole 0.254, TOP to BOTTOM, 173 vias

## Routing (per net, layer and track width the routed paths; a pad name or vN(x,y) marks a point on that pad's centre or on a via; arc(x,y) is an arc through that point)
0V9_PG: length 28.9
  TOP w0.254: PR383.1 136.86,65.47 133.86,65.47 133.1,64.71 130.43,64.71 v2(128.97,63.25)
  TOP w0.305: PR383.1 137.28,65.89 PU10.5
  BOTTOM w0.254: v2(128.97,63.25) 128.65,62.93 128.65,59.12 127.64,58.1 R975.1
1V9_PG: length 18
  TOP w0.305: PU16.1 69.48,73.09 69.18,72.79 PC385.1 ; PC385.1 67.13,72.79 64.83,70.48 v1(63.31,70.48) ; PC385.1 PR467.1 ; PU15.6 59.24,75.37 v1(59.25,75.37)
  BOTTOM w0.305: v1(63.31,70.48) 61.85,70.48 58.88,73.45 PR463.2
  BOTTOM w0.508: PR463.2 58.47,73.47 PR465.1 PC485.1 v1(59.25,75.37)
1V35_PG: length 51.8
  TOP w0.254: v1(131.7,71.69) 131.7,71.01 ; v1(141.48,45.78) 140.34,44.64 140.34,41.85 140.02,41.53 PR462.1 PC358.1 138.09,41.17 PU14.1
  TOP w0.305: PR352.1 134.38,70.36 135.45,70.36 135.77,70.03 PU10.11
  TOP w0.508: PR352.1 PC430.1 131.7,71.01 PR380.2
  L3 w0.254: v1(131.7,71.69) 131.7,72.96 132.21,73.47 139.57,73.47 141.48,71.56 v1(141.48,45.78)
3V3_PG: length 123.2
  TOP w0.127: v1(95.25,94.3) 96.2,95.25 97.54,95.25 98.1,94.68 PR469.2 ; PR610.1 41.93,78.41 v2(42.23,78.11) ; v1(75.59,60.61) v1(84.39,69.41) v1(89.79,74.8) ; v1(57.15,60.6) v1(48.96,60.6)
  TOP w0.254: PU17.6 99.38,91.5 98.74,92.14 PR471.1 PC487.1 PR469.2
  TOP w0.305: PR610.1 41.81,78.98 PU40.5 ; PU16.6 70.48,75.38 v1(70.42,75.44)
  L3 w0.127: v1(72.96,70.99) 74.74,69.22 84.2,69.22 v1(84.39,69.41) ; v2(42.23,78.11) 48.9,78.11 49.15,77.85 49.15,60.79 v1(48.96,60.6) ; v1(75.59,60.61) 57.15,60.61 v1(57.15,60.6) ; v1(95.25,94.3) 93.98,93.03 93.98,78.99 v1(89.79,74.8)
  BOTTOM w0.127: v1(72.96,70.99) 70.37,73.58 PR466.2
  BOTTOM w0.508: v1(70.42,75.44) 70.36,75.5 PC486.1 PR468.1 69.77,73.6 PR466.2
AVDDH_PHY0: length 4.2
  TOP w0.203: E1U1.7 v1(77,100.58) ; v1(74.32,100.59) 74.2,100.47 E1U1.14 ; E1U1.1 v1(79.4,100.56)
  TOP w0.305: E1C41.1 74.42,100.69 v1(74.32,100.59) ; v1(79.4,100.56) 79.54,100.7 E1C39.1 ; v1(77,100.58) 76.73,100.84 E1C40.1
AVDDH_PLL0: length 0.8
  TOP w0.203: E1U1.64 v1(79.35,97.49)
AVDDL_PHY0: length 1.5
  TOP w0.203: E1U1.13 v1(74.6,99.07) ; v1(76.75,99.05) 76.6,99.2 E1U1.8
AVDDL_PLL0: length 0.9
  TOP w0.203: v1(80.92,96.98) 80.82,97.09 E1U1.63
GND: length 901.6
  TOP w0.102: 106.93,54.35 106.94,54.34 106.94,54.35 ; U1.AE22 101.76,54.74 102.08,55.07 ; U1.AH11 106.51,55.59 106.63,55.47 106.63,55.06 106.94,54.75 ; 107.81,55.18 107.37,55.18 106.94,54.75 ; U1.K29 98.48,47.75 97.76,47.75 97.3,47.29 v1(97.05,47.29) ; 106.94,54.75 106.94,54.35 ; v3(105.98,41.86) 105.8,42.04 105.11,42.04 104.78,42.37 104.78,42.98 v3(104.93,43.13) ; v1(114.94,51.59) 114.52,51.59 114.3,51.37 111.67,51.37 111.54,51.24 U1.V1 ; v1(100.85,55.83) 100.9,55.89 ; 106.94,54.35 U1.AE10 ; U1.AB1 110.66,53.21 112.39,53.21 v1(112.59,53.4)
  TOP w0.127: v4(93.83,50.88) 93.05,51.66 91.85,51.66 ; 104.93,43.21 104.78,43.36 104.78,44.09 U1.A15 ; v1(123.19,43.81) 123.14,43.81 ; U1.Y1 110.42,52.1 111.02,52.1 111.25,52.32 113.31,52.32 v1(113.74,52.76) ; v4(90.68,47.43) 90.75,47.36 ; v1(105.03,57.28) 105.47,57.72 105.47,60.58 v1(105.06,60.99) ; v1(105.03,57.28) 104.81,57.06 104.81,55.61 104.78,55.59 U1.AH15 ; v1(105.03,57.28) 104.58,57.72 104.58,59.94 103.82,60.71 103.82,63.5 v1(102.93,64.39) ; 100.75,48.96 100.37,48.96 99.76,49.57 99.76,49.94 ; 91.85,51.66 91.69,51.82 89.28,51.82 v4(89.15,51.69) ; 91.85,51.66 v4(91.88,51.63) ; E1C88.2 69.47,100.06 v2(69.47,100.71) ; U13.G1 98.68,19.99 v1(98.98,19.68) ; U1.AH17 103.92,56.55 103.44,57.02 v1(103.44,57.34) 103.76,57.66 103.76,58.4 R154.2 ; 98.52,49.51 98.51,49.51 ; 98.51,49.51 U1.P29 ; 98.51,49.51 96.95,49.51 v3(96.88,49.58) ; v1(105.85,56.52) 105.65,56.31 105.65,55.59 ; v1(63.63,37.27) 63.5,37.4 62.55,37.4 62.42,37.27 62.42,36.85 U601.35 ; v4(83.69,16.64) 83.69,16.64 ; v4(86.42,13.91) 86.42,13.91 ; v1(101.35,60.2) 101.35,61.53 99.12,63.75 90.36,63.75 v1(88.77,62.17) ; v1(90.81,62.17) 91.63,62.99 98.74,62.99 100.01,61.72 v1(100.01,60.2) ; 105.65,55.59 U1.AH13 ; 105.65,55.59 105.65,55.59 ; SC512.2 126.06,91.05 ; R613.2 v1(64.45,39.1) ; v1(112.85,48.07) 112.25,48.07 111.62,48.64 110.42,48.64 U1.M1 ; U601.1 63.33,33.59 v4(63.41,33.51) ; 121.3,45.66 v1(121.35,45.66) ; 104.39,10.67 v4(104.4,10.67)
  TOP w0.152: U13.J8 91.77,21.59 91.77,21.34 92.16,20.95 92.16,20.38 91.77,19.99 ; U12.G1 117.88,19.96 119.34,19.96 v4(119.37,19.99) ; U13.J2 96.57,21.59 96.97,22 97.99,22 98.34,22.35 98.34,23.28 v1(98.61,23.54) ; U12.J8 112.14,21.59 112.53,21.98 112.53,22.76
  TOP w0.178: v1(119.4,22.85) 118.54,21.99 117.34,21.99 116.94,21.59 U12.J2 ; U601.30 61.16,31.87 v4(61.18,31.85) ; v1(98.68,27.28) 97.43,27.28 97.37,27.19 U13.T1 ; v1(119.74,25.26) 119.34,25.65 117.8,25.65 117.74,25.59 U12.P1 ; v1(98.08,55.53) U1.AG29 ; U1.H3 109.04,46.92 ; 112.53,22.76 v1(112.53,22.76) ; v3(104.93,43.13) 104.93,43.21
  TOP w0.203: v1(109.27,45.4) 109.27,45.57 U1.E4 ; v3(101.63,50.7) 101.68,50.7 102.03,51.05 U1.U22 ; U1.E4 108.75,45.81 108.23,45.29 U1.C6 ; U1.E4 108.66,46.19 U1.F6 108.53,46.41 109.04,46.92 ; U1.W24 101.21,51.96 v1(101.6,52.35) ; U12.E1 117.74,18.39 117.66,18.47 117.01,18.47 116.94,18.39 U12.E2 ; E1U1.60 80.85,95.89 v1(80.87,95.92) ; 90.96,25.59 90.97,25.59 ; 90.96,25.59 88.9,25.59 v1(88.39,26.07) ; 90.96,25.59 U13.P9 ; U1.AA16 104.89,53.11 105.7,53.11 U1.AC12 ; E1U1.47 v1(77.8,92.75) ; 90.97,19.99 91.06,19.89 91.67,19.89 91.77,19.99 U13.G8 ; U1.W14 105.7,52.3 v1(106.51,52.3) ; U1.U12 U1.U10 ; U1.H16 104.52,46.94 104.52,46.24 U1.F16 ; E1U1.43 v1(76.2,92.75) ; E1U1.67 79.58,98.69 v1(79.27,98.38) ; U1.AA4 109,52.36 v1(109,52.1) 109,51.85 U1.W4 ; 100.75,48.96 v1(100.77,48.96) 100.84,49.02 100.84,49.05 101.21,49.42 U1.P24
  TOP w0.254: U1.K14 105.28,47.83 104.98,48.13 v1(104.92,48.13) 104.92,48.19 104.49,48.63 U1.M16 ; U1.AD1 110.42,53.7 111.74,53.7 113.51,55.47 v2(114.28,55.47) ; U12.D8 112.14,17.59 v1(111.74,17.99) 112.14,18.39 U12.E8 ; U904.8 U904.11 134.47,23.69 U904.4 ; 111.33,15.19 111.34,15.19 ; 111.33,15.19 U12.A9 ; 111.33,15.19 v1(110.94,15.59) ; U1.AH28 99.01,55.9 v1(98.65,56.26) ; U12.G8 U12.G9 110.82,19.99 v1(110.79,20.02) ; 91.76,17.59 U13.D8 ; 91.76,17.59 v1(91.37,17.99) 91.77,18.39 U13.E8 ; 91.76,17.59 91.77,17.59 ; U1.F25 100.25,46.33 100.25,46.56 99.9,46.91 99.36,46.91 U1.H27 ; U1.F25 100.41,46.19 v1(100.81,46.58) 101.22,46.99 U1.H24 ; U1.F25 100.89,45.69 U1.D24 100.89,45.32 U1.C25 ; U1.F25 100.21,46.19 U1.E26 ; U1.T8 107.71,50.25 v1(107.33,49.87) 107.35,49.87 107.72,49.51 U1.P8 ; v1(98.88,43.39) 99.02,43.53 99.02,44.09 U1.A28 ; SC147.2 113.38,89.77 113.64,89.51 114.22,89.51 114.55,89.84 SC518.2 ; v1(98.61,23.54) 98.61,23.73 98.16,24.18 97.56,24.18 97.37,23.99 U13.M1 ; v1(98.55,17.13) 98.1,17.59 97.37,17.59 U13.D1 ; v1(104.91,50.62) 104.46,51.06 U1.U16 ; v1(104.91,50.62) 104.84,50.62 104.48,50.25 U1.T16 ; v1(104.91,50.62) 105.27,50.25 U1.T14 ; U12.B9 111.34,15.99 v1(110.94,16.39) ; 100.4,51.05 100.02,51.05 99.76,50.8 ; 100.4,51.05 100.4,51.05 ; 100.4,51.05 U1.U25 ; v1(103.25,52.26) 103.65,52.66 U1.AA18 ; v1(110.95,44.12) 110.94,44.13 110.87,44.13 110.42,44.58 U1.B1 ; v4(118.85,15.9) 118.76,15.99 117.74,15.99 U12.B1 ; U12.T1 117.74,27.19 118.22,27.19 118.87,26.54 v1(119.13,26.54) ; U1.AA18 U1.AC20 ; U1.AA18 U1.AA16 ; U1.AC20 102.84,53.5 ; U1.AC20 U1.AC22 ; U12.T9 111.34,27.19 110.99,27.45 v1(110.71,27.45) ; v1(104.78,45.75) 105.22,45.33 U1.D14 ; U13.P1 97.37,25.59 97.69,25.91 98.55,25.91 99.36,26.77 v1(99.68,26.77) ; v1(106.51,52.3) U1.AA10 ; U12.F9 111.33,19.19 ; 111.33,19.19 111.34,19.19 ; 111.33,19.19 110.84,19.19 v1(110.79,19.07) ; v1(110.35,56.02) U1.AH2 ; U13.B9 90.97,15.99 v1(90.57,15.59) 90.97,15.19 U13.A9 ; U1.R26 99.76,49.94 99.76,50.8 ; U12.B3 116.12,15.99 v1(115.77,16.33) ; 111.34,23.99 111.33,23.99 ; 111.33,23.99 U12.M9 ; 111.33,23.99 110.79,23.99 110.11,23.37 v1(110.11,22.76) ; v1(90.2,19.18) 90.97,19.19 U13.F9 ; v1(90.4,20.24) 90.65,19.99 U13.G9 90.96,19.99 90.97,19.99 ; U13.B1 97.37,15.99 v1(97.9,15.99) ; U1.AF5 108.56,54.52 108.2,54.17 108.2,54.03 v1(108.18,54) 108.18,53.85 U1.AC6 ; v1(119.4,22.85) 119.4,23.52 118.94,23.99 117.74,23.99 U12.M1 ; v1(109.41,25.63) 109.41,25.68 109.43,25.7 111.22,25.7 111.34,25.59 U12.P9 ; v1(110.84,55.34) 110.62,55.12 110.49,55.12 110.47,55.1 U1.AG1 110.42,55.09 ; U13.T9 90.97,27.19 90.58,27.57 v1(90.3,27.57) ; v1(104,45.84) U1.F18 ; 99.76,50.8 U1.U26 ; U1.B29 98.19,44.27 v1(98.19,44) ; U1.A2 109.92,44.09 109.92,43.62 109.96,43.59 v1(109.96,43.46) ; U12.D1 117.74,17.59 118.16,18.01 v4(118.26,18.01) 117.88,18.39 117.74,18.39 ; U13.B3 95.76,16 v1(95.37,16.39) ; 107.9,57.27 v1(107.89,57.28) ; U1.AE16 104.37,54.35 104.78,53.95 v1(104.78,53.91) 104.79,53.91 105.21,54.34 U1.AE14
  TOP w0.305: C116.2 v1(134.23,13.3) ; C8566.2 26.34,62.69 v2(26.29,62.74) ; v1(103.25,52.26) 103.27,52.26 U1.W18 ; PU40.9 37.72,78.48 v2(37.59,78.61) ; 90.97,23.99 90.96,23.99 ; 90.96,23.99 90.69,23.99 90.17,23.47 v1(90.17,22.86) ; 90.96,23.99 U13.M9 ; 100.4,44.81 100.4,44.82 ; 100.4,44.82 U1.C25 ; 100.4,44.82 100.4,44.83 ; U1.H8 v1(107.33,46.62) ; U1.W8 107.72,51.87 107.31,51.46 v1(107.31,51.44) 107.29,51.44 106.91,51.05 U1.U10 ; E1C75.1 E1C74.1 v4(72.91,91.19) ; C29.2 29.42,62.69 v2(29.46,62.74) ; U1.M20 v1(103.2,48.26) U1.K18 ; U1.D24 100.9,45.34 100.9,45.33 ; PU10.9 136.77,69.97 v2(136.91,70.1) ; U1.AE22 U1.AE24 100.62,54.35 v1(100.4,54.13) U1.AC25 ; U1.F16 104.47,46.18 104.78,45.84 v1(104.78,45.75) ; 106.91,47.8 106.91,47.81 ; 106.91,47.81 106.49,48.23 v1(106.49,48.32) ; 106.91,47.81 U1.K10 ; v1(108.67,22.78) 108.67,23.11 108.43,23.34 R135.2 ; U1.T18 103.74,50.16 104.38,50.16 U1.T16 ; C28.2 v2(138.75,56.58) ; TP30.1 v2(84.99,44.04) ; v1(98.15,18.41) 98.12,18.39 U13.E1 U13.E2
  TOP w0.381: v1(86.16,100.64) 86.16,99.82 EY300.2 86.84,99.87 v1(86.84,100.64) ; 45.19,162.08 SW800.4 ; SW800.4 46.36,163.25 ; SW800.4 44.02,163.25 ; SW800.4 45.19,164.42 ; U602.15 34.35,31.09 ; U602.15 33.22,32.22 ; U602.15 33.22,29.96 ; U602.15 32.08,31.09 ; U602.13 55.41,36.19 55.41,36.2 55.67,36.2 56.13,36.66 v4(56.13,36.77) ; 46.44,164.73 SW800.2 ; SW800.2 47.46,165.75 ; SW800.2 46.44,166.77 ; SW800.2 45.42,165.75 ; 32.08,37.69 U602.16 ; U602.16 33.22,38.82 ; U602.16 33.22,36.56 ; U602.16 34.35,37.69 ; 134.52,24.59 U904.12 ; U904.12 134.87,24.95 ; U904.12 134.87,24.24 ; SW800.3 53.36,163.25 ; SW800.3 52.19,162.08 ; SW800.3 52.19,164.42 ; SW800.3 51.02,163.25 ; J7.4 143.38,48.78 ; J7.4 143.38,46.72 ; J7.4 142.35,47.75 ; J7.4 144.41,47.75 ; EY300.4 83.74,96.32 v1(83.31,96.32) ; U602.8 52.66,33.21 ; U602.8 51.69,32.24 ; U602.8 53.62,32.24 ; J1.5 143.97,84.71 ; J1.5 142.94,83.68 ; J1.5 142.94,85.74 ; J1.5 141.91,84.71 ; SF604.1 116.72,106.4 ; SF604.1 116.72,104.93 ; SF604.1 117.76,105.67 ; SF604.1 115.68,105.67 ; 52.66,35.78 U602.14 ; U602.14 52.66,37.71 ; U602.14 53.62,36.74 ; U602.14 51.69,36.74 ; U602.10 55.66,33.79 55.95,33.5 v4(55.95,33.01) ; U602.3 55.38,28.09 55.87,28.57 v4(56.01,28.57) ; 39.58,31.09 U602.17 ; U602.17 41.85,31.09 ; U602.17 40.72,29.96 ; U602.17 40.72,32.22 ; U904.13 135.23,23.59 ; U904.13 134.87,23.24 ; U904.13 134.87,23.95 ; U904.13 134.52,23.59 ; v4(55.95,30.22) 55.68,30.49 U602.6
  TOP w0.457: 126.87,39.82 v4(126.87,36.32) v4(126.87,32.83) v4(126.87,30.54) v4(126.87,27.53) 126.94,27.47 v4(126.94,21.41) v4(126.94,19.52) v4(126.94,16.64) 126.94,15.75 v4(124.08,12.89) 121.86,10.67 v4(119.06,10.67) ; 126.87,39.82 126.87,40.08 v1(119.53,47.42) v4(118.25,48.7) ; 126.87,39.82 v1(126.88,39.82) ; v4(93.04,49.71) 93.04,49.66 88.85,45.47 v4(88.77,45.47) v4(87.12,43.81) v4(84.9,41.59) ; v4(94.36,10.67) 89.66,10.67 v4(89.64,10.69) 81.22,19.11 v4(81.22,20.32) v4(81.22,23.62) ; 99.38,10.67 v4(99.38,10.67) ; v4(110.11,10.67) 110.11,10.67
  TOP w0.508: C1011.2 v2(126.56,55) ; CE31.2 v2(55.56,16.19) ; v2(48.07,12) 48.07,12 Q6.E 48.07,13.18 SC267.1 ; v2(124.24,11.65) 125.5,12.9 C232.2 ; R182.2 v2(78.93,48.83) ; v4(89.25,47.53) 88.82,47.96 88.82,48.69 89.8,48.69 v4(90.11,48.39) ; v1(135.02,87.02) 134.18,87.02 SY3.4 134.17,86.32 v1(135.02,86.32) ; PC430.2 v2(132.78,72.58) ; C162.2 88.78,51.69 v4(89.15,51.69) ; v2(138.87,53.98) 138.88,53.98 D904.2 ; CE77.2 v2(56.58,3.62) ; SC274.1 107.25,91.88 v4(107,92.14) ; CE25.2 v1(81.47,16.26) ; CE34.2 53.66,14.49 Q7.E v2(53.66,11.87) ; SC504.2 107.6,86.71 v1(107.7,86.8) 107.81,86.91 SC129.2 ; v1(70.68,97.6) 70.87,97.41 E1C51.1 ; CE35.2 66.41,15.54 v1(66.55,15.68) ; v1(131.97,89.62) 131.52,89.17 SY3.2 ; v2(132.21,80.77) SC254.2 132.14,79.77 U108.GND ; v1(111.4,90.4) 111.44,90.36 SC150.2 ; v2(135.64,49.72) 135.53,49.62 C1003.2 ; SR72.2 119.81,85.04 SC136.2 119.66,84.49 118.26,83.08 v1(118.26,82.37) ; R192.2 v2(119.46,54.99) ; SC239.1 110.17,88.9 v1(110.3,89.03) 111.05,89.77 SC150.2 ; C973.2 v2(100.97,11.81) ; v2(35.94,13.21) 35.97,13.18 Q2.E 36.83,14.55 CE22.2 ; CE80.2 v2(76.45,3.49) ; SC150.2 SC519.2 ; CE32.2 58.87,14.49 Q8.E 58.87,12.13 v2(58.99,12) ; R156.2 77.3,48.83 v2(77.32,48.82) ; v2(128.91,53.91) 128.9,53.91 C1010.2 C1009.2 ; R186.2 v1(118.92,51.94) ; v1(106.49,60.77) 106.49,59.82 106.68,59.63 R621.2 ; SC240.1 v1(106.43,87.95) ; SC147.2 SC519.2 ; SC519.2 112.35,89.79 SC446.2 ; C1002.2 135.23,51.52 v2(135.64,51.12) ; v4(106.93,90.38) 107.39,89.92 SC268.1 SC273.1 ; D903.2 140.84,48.19 v2(140.84,48.2) ; v1(123.85,53.29) 123.83,53.31 R274.1 ; CE73.2 46.48,3.56 v2(46.42,3.49) ; CE79.2 v2(66.55,4.7) ; R978.2 v2(132.21,55.81) ; v1(77.15,15.56) 77.14,15.54 CE28.2 ; SC520.2 v2(140.69,92.31) ; PU908.2 v2(132.97,53.99) ; R190.2 94.69,55.55 v1(95.35,54.9) ; C1008.2 135.57,53.91 v2(135.64,53.98) ; C925.2 v2(139.83,57.59) ; CE21.2 v2(38.73,16.26) ; CE23.2 v2(44.01,16.26) ; C1007.2 v2(134.79,56.96) ; C1005.2 v2(126.36,50.61) ; R976.2 133.06,51.52 v2(132.92,51.38) ; v1(79.57,11.87) Q4.E 79.57,14.62 CE26.2 ; v2(30.73,13.14) 30.77,13.18 Q1.E 31.69,14.49 CE19.2 ; v4(85.22,47.31) 86.06,48.15 86.06,48.34 85.9,48.34 85.15,49.09 v4(85.03,49.09) ; CE76.2 86.8,4 v2(86.74,3.94) ; SC264.2 v2(127.13,75.95) ; v2(129.92,84.96) 129.98,85.03 SC165.2 ; SC219.2 SC218.2 118.73,96.39 SR485.2 118.73,94.14 v1(118.59,94.01) ; SR129.1 v4(106.43,88.9) ; v1(74.49,12) Q5.E 74.42,13.24 CE27.2 ; CE29.2 v2(47.12,13.72) ; C161.2 v4(90.87,49.97) ; PR352.2 v2(133.73,72.58) ; v1(69.28,12.06) 69.41,12.19 Q10.E 69.41,14.55 CE36.2 ; CE74.2 v2(56.52,4.7) ; CE75.2 v2(96.65,4) ; v1(96.27,59.75) R184.2 ; v1(95.31,59.75) R194.2 ; v2(64.2,12) Q9.E 64.2,14.43 CE38.2 ; CE72.2 v2(46.42,4.7) ; R136.2 87.77,26.07 v1(88.39,26.07) ; v2(41.21,13.21) 41.25,13.24 Q3.E 42.1,14.49 CE24.2 ; v2(33.91,16.38) 33.59,16.07 CE20.2 ; CE37.2 v1(71.31,16.13) ; SC265.2 108.19,79.11 v1(107.95,78.87) ; SR74.1 v1(110.3,87.95) ; v2(127.05,51.42) R983.2 ; CE30.2 v2(49.97,16.32) ; SC521.2 v2(140.77,89.61) ; v4(107,93.73) 107.71,93.01 SC275.1 ; R188.2 v1(118.17,50.98) ; CE81.2 v2(76.45,4.7) ; SC266.2 v1(108.71,75.82) ; CE33.2 61.29,16 v2(61.34,16) ; CE78.2 v2(66.61,3.56) ; PU902.2 v2(133.03,49.7)
  L2 w0.381: 116.72,104.93 SF604.1 ; SF604.1 117.76,105.67 ; SF604.1 116.72,106.4 ; SF604.1 115.68,105.67 ; 51.77,27.04 U602.1 ; U602.1 53.54,27.04 ; U602.1 52.66,27.93 ; U602.1 52.66,26.15 ; U904.12 135.31,24.59 ; U904.12 134.87,25.02 ; U904.12 134.44,24.59 ; U904.12 134.87,24.16 ; U904.13 135.31,23.59 ; U904.13 134.44,23.59 ; U904.13 134.87,23.16
  L3 w0.127: 111.38,62.55 115.31,62.55 v1(115.51,62.35) ; 111.38,62.55 91.88,62.55 91.12,61.79 v1(91.12,60.71) ; 111.38,62.55 v1(111.57,62.36) ; v1(66.06,75.59) 66.06,71.23 69.95,67.34 108.8,67.34 v1(109.09,67.63) ; v2(31.5,148.78) 31.75,148.53 38.04,148.53 39.43,149.92 39.43,152.97 v2(40.01,153.54) ; v1(72.9,69.15) 73.09,68.96 84.77,68.96 v1(85.03,69.22) ; v2(28.45,147.19) 29.02,147.76 38.73,147.76 v2(38.99,148.02) ; v2(29.91,146.05) 30.67,146.81 41.15,146.81 43.81,149.48 v2(44.45,149.48)
  L3 w0.254: 4.06,96.27 4.06,96.58 v2(3.84,96.81) 4.06,97.03 4.06,104.84 v2(3.84,105.06) 4.06,105.28 4.06,107.7 5.91,109.54 v2(5.91,109.92)
  L3 w0.381: U602.1 53.54,27.04 ; U602.1 52.66,27.93 ; U602.1 52.66,26.15 ; U602.1 51.77,27.04 ; SF604.1 116.72,106.4 ; SF604.1 115.68,105.67 ; SF604.1 116.72,104.93 ; SF604.1 117.76,105.67
  BOTTOM w0.102: v3(105.98,41.86) 105.98,41.92 106.43,42.37 R132.1 ; 95.4,19.63 95.25,19.63 94.74,20.14 94.74,20.24 93.19,21.79 88.7,21.79 88.52,21.97
  BOTTOM w0.127: 109.94,81.25 109.92,81.23 SC501.2 ; 104.35,41.43 104.37,41.44 105.41,41.44 105.83,41.86 v3(105.98,41.86) ; v1(109.27,96.16) 108.87,96.57 SC235.1 ; 107.06,81.23 SC500.2 ; v4(118.25,48.7) 117.55,49.4 109.8,49.4 109.29,48.89 C203.2 ; E1C65.1 72.21,99.62 v1(72.14,99.69)
  BOTTOM w0.178: 96.42,17.12 93.88,19.66 v1(93.62,19.66) ; 86.9,41.25 87.08,41.43 104.35,41.43 ; v1(110.79,20.02) 110.82,20.04 112.95,20.04 113.32,19.67 114.29,19.67 114.82,20.21 115.33,20.21
  BOTTOM w0.203: C153.2 105.54,49.52 105.85,49.22 105.85,49.09 C218.2 ; C189.2 97.45,53.02 v1(96.91,52.49) ; 96.42,17.12 96.82,17.12 96.84,17.13 ; v1(90.3,27.57) 90.3,27.68 C115.2 ; v1(104.92,48.13) 104.92,48.19
  BOTTOM w0.254: 100.28,47.68 C168.2 ; C960.2 111.32,15.2 v1(110.94,15.59) ; C103.2 119.13,26.49 v1(119.13,26.54) ; C105.2 111.74,18.45 v1(111.74,17.99) ; C102.2 110.62,27.56 110.67,27.5 v1(110.71,27.45) ; v1(114.94,51.59) 114.58,51.59 114.05,51.06 C239.2 112.44,51.06 112.07,51.43 C227.2 111.58,51.43 111.21,51.06 C193.1 110.83,50.94 C231.2 C223.2 C219.2 ; v1(110.94,16.39) 110.94,16.4 110.77,16.56 C95.2 ; v1(103.25,52.26) 103.14,52.15 C197.2 ; v1(119.74,25.26) 119.65,25.18 C104.2 ; 115.33,20.21 v1(115.33,20.2) ; C978.2 126.82,27.48 v4(126.87,27.53) ; C980.2 126.86,19.52 v4(126.94,19.52)
  BOTTOM w0.305: C205.2 98.06,16.15 v1(97.9,15.99) ; v1(95.37,16.39) 95.37,16.39 C141.2 ; v4(99.01,14.33) 98.87,14.46 C200.2 ; C956.2 88.85,22.3 88.52,21.97 ; v1(104.78,53.91) 104.89,54.03 C180.1 ; C195.2 99.18,19.49 v1(98.98,19.68) ; C111.2 99.26,20.2 99.26,19.96 v1(98.98,19.68) ; C98.2 109.81,22.75 110.1,22.75 v1(110.11,22.76) ; C142.2 115.15,16.93 ; v4(118.85,15.9) 119.41,16.47 C958.2 ; 90.07,20.57 v1(90.4,20.24) 90.83,19.81 C106.2 ; C100.2 95.86,46.91 v1(96.24,47.29) ; C959.2 97.89,20.24 98.45,19.68 v1(98.98,19.68) ; C634.2 v1(126.81,72.26) ; v4(119.98,15.26) 119.98,15.27 C94.2 ; v1(99.48,25.23) 99.47,25.25 C113.2 ; C159.2 99.61,26.71 v1(99.68,26.77) ; C110.2 C112.2 91.43,17.92 v1(91.37,17.99) ; v4(115.57,18.97) 115.62,19.02 115.62,19.05 C99.2 ; v1(109.18,18.31) 109.18,18.41 v1(110.79,20.02) ; v4(84.9,41.59) v4(82.55,39.24) 81.28,37.97 v4(81.28,34.42) 81.22,34.35 v4(81.22,30.61) v4(81.22,27.56) v4(81.22,23.62) ; v1(90.57,15.59) 90.57,15.46 90.53,15.42 C961.2 ; C114.2 111.58,43.48 v1(110.95,44.12) ; v1(107.57,18.62) 107.31,18.36 v1(105.46,18.36) v1(102.39,18.36) 98.2,18.36 v1(98.15,18.41) 98.09,18.36 96.88,18.36 95.61,19.63 95.4,19.63 ; C957.2 108.51,21.18 v4(108.81,20.88) 108.88,20.81 C96.2 ; v4(124.36,35) 124.73,35 C979.2 ; v1(90.2,19.18) 91.91,19.18 C140.2 ; C24.2 102.93,31.02 v1(102.94,31.02) ; v1(104.91,50.62) 104.72,50.43 C229.1 ; v4(119.37,19.99) 119.34,20.03 C101.2
  BOTTOM w0.356: 90.07,20.57 84.26,20.57 v4(81.22,23.62) ; v4(108.81,20.88) 108.81,19.86 v1(107.57,18.62) ; v3(104.93,43.13) 104.35,42.55 85.85,42.55 v4(84.9,41.59)
  BOTTOM w0.381: 45.19,162.08 SW800.4 ; SW800.4 45.19,164.42 ; SW800.4 44.02,163.25 ; SW800.4 46.36,163.25 ; U602.15 33.22,32.73 ; U602.15 34.85,31.09 ; U602.15 31.58,31.09 ; U602.1 52.66,28.01 ; U602.1 52.66,26.08 ; U602.1 53.62,27.04 ; U602.16 33.22,39.33 ; U602.16 31.58,37.69 ; U602.16 34.85,37.69 ; U602.16 33.22,36.05 ; SW800.3 53.36,163.25 ; SW800.3 52.19,162.08 ; SW800.3 52.19,164.42 ; SW800.3 51.02,163.25 ; U602.14 52.66,37.71 ; U602.14 53.62,36.74 ; U602.14 52.66,35.78 ; 116.72,104.93 SF604.1 ; SF604.1 116.72,106.4 ; SF604.1 115.68,105.67 ; SW800.2 47.46,165.75 ; SW800.2 46.44,166.77 ; SW800.2 46.44,164.73 ; SW800.2 45.42,165.75 ; 142.35,47.75 J7.4 ; J7.4 143.38,48.78 ; J7.4 144.41,47.75 ; J7.4 143.38,46.72 ; U904.12 135.31,24.59 ; U904.12 134.44,24.59 ; U904.12 134.87,25.02 ; 39.08,31.09 U602.17 ; U602.17 40.72,32.73 ; U602.17 42.35,31.09 ; 142.94,83.68 J1.5 ; J1.5 141.91,84.71 ; J1.5 143.97,84.71 ; J1.5 142.94,85.74 ; 134.44,23.59 U904.13 ; U904.13 134.87,23.16 ; U904.13 135.31,23.59 ; 53.62,32.24 U602.8 52.66,33.21
  BOTTOM w0.432: 100.67,17.13 103.59,17.13 ; 100.67,17.13 v1(98.55,17.13) 96.84,17.13 ; 100.67,17.13 v1(100.67,17.12) ; 103.59,17.13 v1(103.59,17.12) ; 103.59,17.13 106.44,17.13 ; v1(106.44,17.12) 106.44,17.13 ; 106.44,17.13 108.01,17.13 v1(109.18,18.31)
  BOTTOM w0.483: 86.9,41.25 82.67,37.02 82.67,24.17 84.86,21.97 88.52,21.97 88.52,21.97
  BOTTOM w0.508: 107.06,81.23 107.06,80.83 v1(107.38,80.52) ; SC246.1 SR79.1 v4(106.93,90.38) ; SC501.2 v2(109.92,80.33) ; U602.17 40.72,29.25 v4(40.72,29.13) ; SC253.1 SR40.1 107.68,92.14 v4(107,92.14) ; v1(128.02,91.95) 127.84,92.12 SC236.1 SR119.1 ; v1(115.77,16.33) 115.75,16.33 115.15,16.93 C974.2 ; v4(124.36,35) 124.08,35.28 C144.2 ; v4(51.42,36.77) 51.45,36.74 U602.14 ; v1(112.85,48.07) 112.38,47.6 112.27,47.6 C272.2 ; SC240.1 v1(106.43,87.95) ; v1(110.3,89.03) 110.17,88.9 SC239.1 ; SC247.1 SR75.1 107.2,93.93 v4(107,93.73) ; U602.8 51.51,32.24 v4(51.49,32.26) ; v1(108.29,84.41) 108.23,84.48 SC250.2 107.55,84.5 SC252.2 ; U602.16 33.2,37.71 v4(31.35,37.71) ; SR74.1 v1(110.3,87.95) ; EC20.2 v2(131.19,96.65) ; SC242.2 v2(128.14,93.98) 128.02,93.98 128,93.96 SC249.1 SR50.1 ; SC248.1 v1(107.7,86.8) ; SC435.1 SR124.1 v2(128.14,95.74) ; E1C84.1 81.97,99.3 v1(81.92,99.25) ; C972.2 94.78,15.51 95.37,16.09 v1(95.37,16.39) ; SR129.1 v4(106.43,88.9) ; U602.1 v4(51.46,27.04) ; v4(105.12,19.6) C971.2 ; SR390.2 v1(112.78,76.1) ; v4(33.2,29.18) 33.22,29.19 U602.15 ; SC502.2 112.78,80.77 v1(112.97,80.58)
  vias: v1(46.8,44.45) v1(48.26,33.72) v1(48.48,24.32) v1(49.4,58.61) v1(49.4,55.12) v1(49.4,31.88) v1(49.47,51.18) v1(49.47,41.97) v1(49.66,61.15) v1(49.85,47.62) v1(50.99,61.15) v1(50.99,59.94) v1(50.99,57.34) v1(50.99,51.63) v1(50.99,43.69) v1(51.05,48.77) v1(51.47,24.96) v1(51.88,22.67) v1(52.07,54.04) v1(52.26,58.86) v1(52.32,56.52) v1(52.39,61.15) v1(54.02,23.39) v1(54.29,46.74) v1(54.93,22.68) v1(55.24,59.69) v1(55.24,56.96) v1(55.44,74.93) v1(55.37,54.36) v1(55.37,50.8) v1(55.63,77.53) v1(55.63,71.69) v1(55.82,64.45) v1(56.01,87.88) v1(56.13,31.31) v1(56.2,80.01) v1(56.2,40.01) v1(56.39,81.79) v1(56.39,81.03) v1(56.45,61.09) v1(57.09,23.11) v1(57.59,73.79) v1(57.59,73.09) v1(57.85,77.66) v1(57.85,76.9) v1(57.85,76.07) v1(57.91,48.77) v1(57.91,45.4) v1(58.04,52.45) v1(57.98,42.04) v1(58.17,86.87) v1(58.29,39.12) v1(58.86,60.01) v1(58.99,54.48) v1(59,23.04) v1(59.05,28.96) v1(59.5,50.8) v1(59.5,38.73) v1(59.56,46.8) v1(59.56,44.26) v1(59.56,41.47) v1(59.88,77.47) v1(59.94,52.77) v1(59.89,29.57) v1(60.33,74.8) v1(60.33,74.17) v1(60.33,73.53) v1(60.33,72.9) v1(60.53,30) v1(60.64,70.87) v1(60.62,22.9) v1(60.77,76.64) v1(60.77,61.09) v1(60.83,48.26) v1(60.83,45.21) v1(60.83,38.8) v1(60.9,74.8) v1(60.9,74.17) v1(60.9,73.53) v1(60.9,72.9) v1(60.9,42.55) v1(61.02,64.45) v1(61.02,51.56) v1(61.15,39.94) v1(61.28,57.21) v1(61.29,23.9) v1(61.47,69.85) v1(61.47,68.71) v1(61.47,67.63) v1(61.53,66.67) v1(61.59,77.47) v1(61.59,54.55) v1(62.61,91.44) v1(62.61,53.4) v1(62.67,50.8) v1(62.67,46.93) v1(62.67,41.4) v1(63.12,55.88) v1(63.31,59.88) v1(63.56,48.39) v1(63.56,43.37) v1(63.94,102.04) v1(64.01,52.01) v1(64.45,94.87) v1(64.45,50.8) v1(64.45,46.93) v1(64.45,41.34) v1(64.58,99.95) v1(64.64,93.6) v1(64.9,119.25) v1(64.9,54.29) v1(64.96,96.08) v1(64.96,55.69) v1(65.34,61.15) v1(65.41,115.32) v1(65.41,101.03) v1(65.66,108.2) v1(65.66,58.42) v1(65.91,34.8) v1(65.98,33.59) v1(66.1,50.42) v1(66.1,46.74) v1(66.1,42.55) v1(66.17,119.25) v1(66.23,94.11) v1(66.17,92.65) v1(66.23,90.36) v1(66.29,85.53) v1(66.42,55.82) v1(66.55,57.34) v1(66.48,54.48) v1(66.55,53.15) v1(66.93,79.57) v1(66.93,78.3) v1(66.93,77.28) v1(66.93,76.14) v1(66.93,73.79) v1(66.87,64.45) v1(66.87,60.01) v1(67.25,84.07) v1(67.44,34.86) v1(67.44,33.53) v1(67.63,100.14) v1(67.63,97.85) v1(67.69,95.69) v1(67.82,120.02) v1(67.82,118.75) v1(67.75,55.75) v1(68.14,48.58) v1(68.14,42.29) v1(68.2,45.15) v1(68.2,38.29) v1(68.26,73.79) v1(68.39,53.4) v1(68.64,55.18) v1(68.71,92.9) v1(68.83,61.15) v1(68.96,73.79) v1(69.09,77.91) v1(69.09,77.03) v1(69.09,76.2) v1(69.06,32.26) v1(69.22,120.78) v1(69.22,51.88) v1(69.41,49.97) v1(69.41,46.99) v1(69.41,43.43) v1(69.41,40.01) v1(69.41,35.75) v1(69.47,58.61) v1(69.47,54.36) v1(69.6,103.12) v1(69.72,84.14) v1(69.66,57.4) v1(70.29,59.88) v1(70.42,86.04) v1(70.48,92.14) v1(70.87,120.78) v1(70.99,77.85) v1(71.25,86.04) v1(71.31,64.45) v1(71.5,74.99) v1(71.5,74.36) v1(71.5,73.72) v1(71.5,73.09) v1(71.82,84.45) v1(71.75,61.15) v1(71.88,77.03) v1(71.95,71.06) v1(72.07,74.99) v1(72.07,74.36) v1(72.07,73.72) v1(72.07,73.09) v1(72.14,53.47) v1(72.07,52.13) v1(72.39,120.78) v1(72.39,86.04) v1(72.55,101.78) v1(72.71,77.85) v1(72.71,58.61) v1(72.77,66.61) v1(72.9,70.23) v1(73.03,68.01) v1(73.1,98.86) v1(73.1,97.97) v1(73.34,57.4) v1(73.41,86.04) v1(73.53,53.4) v1(73.6,52.2) v1(73.91,120.78) v1(73.87,101.56) v1(73.98,59.88) v1(74.49,58.61) v1(74.61,84.14) v1(74.74,64.45) v1(74.74,53.4) v1(75.06,80.71) v1(75.18,68.01) v1(75.18,61.21) v1(75.5,52.2) v1(75.56,120.78) v1(75.63,57.4) v1(76.14,86.3) v1(76.33,81.22) v1(76.58,53.4) v1(76.96,89.73) v1(77.03,58.61) v1(77.09,120.78) v1(77.09,66.61) v1(77.15,87.44) v1(77.15,86.74) v1(77.15,85.34) v1(77.22,61.09) v1(77.53,81.22) v1(78.11,59.88) v1(78.42,87.44) v1(78.42,86.68) v1(78.42,85.34) v1(78.49,89.79) v1(78.55,52.2) v1(78.56,102.79) v1(78.61,68.01) v1(78.61,64.52) v1(78.74,120.78) v1(79.12,88.84) v1(79.25,92.96) v1(79.38,87.69) v1(79.44,86.8) v1(79.38,85.34) v1(79.63,53.47) v1(79.69,81.34) v1(79.95,58.67) v1(80.06,100.51) v1(80.33,69.79) v1(80.33,64.52) v1(80.26,52.2) v1(80.39,120.78) v1(80.45,73.66) v1(80.58,90.49) v1(80.64,66.61) v1(80.58,61.59) v1(80.71,87.63) v1(80.77,86.74) v1(80.84,85.22) v1(80.77,57.47) v1(80.9,98.63) v1(81.41,79.88) v1(81.72,75.69) v1(81.72,60.2) v1(81.72,53.47) v1(81.92,120.78) v1(81.85,96.84) v1(82.04,68.01) v1(82.36,71.82) v1(82.42,66.61) v1(82.49,84.71) v1(82.55,80.96) v1(82.49,59.31) v1(82.61,90.49) v1(82.61,61.15) v1(82.71,99.22) v1(82.68,96.84) v1(82.68,86.87) v1(82.99,93.73) v1(83.06,94.74) v1(83.31,82.87) v1(83.38,91.25) v1(83.44,64.52) v1(83.44,62.1) v1(83.5,73.03) v1(83.5,60.33) v1(83.57,120.78) v1(83.69,76.71) v1(83.69,68.01) v1(84.07,87.44) v1(84.07,57.72) v1(84.14,53.02) v1(84.23,100.64) v1(84.2,70.1) v1(84.33,55.31) v1(84.56,92.16) v1(84.65,74.04) v1(85.04,100.64) v1(85.03,75.56) v1(85.09,86.8) v1(85.09,81.41) v1(85.22,120.78) v1(85.22,83.76) v1(85.22,71.18) v1(85.41,62.1) v1(85.47,92.01) v1(85.53,66.61) v1(85.92,76.58) v1(85.85,64.52) v1(85.92,61.15) v1(86.04,56.9) v1(86.13,96.07) v1(86.3,57.98) v1(86.42,72.33) v1(86.36,70.61) v1(86.36,55.31) v1(86.74,120.78) v1(86.79,96.07) v1(87.05,94.8) v1(87.05,93.96) v1(87.25,88.84) v1(87.25,85.28) v1(87.44,92.14) v1(87.44,53.02) v1(87.48,99.85) v1(87.48,99.04) v1(87.48,98.2) v1(87.48,97.49) v1(87.5,96.68) v1(87.5,57.98) v1(87.57,62.1) v1(87.57,61.15) v1(87.69,76.96) v1(87.69,56.77) v1(87.69,23.3) v1(87.82,72.07) v1(87.88,66.61) v1(88.01,73.91) v1(88.14,69.28) v1(88.07,64.58) v1(88.33,68.01) v1(88.65,120.78) v1(88.84,57.59) v1(89.03,53.01) v1(89.53,70.74) v1(89.6,73.79) v1(89.6,61.02) v1(89.66,78.68) v1(89.98,64.45) v1(90.3,120.78) v1(90.42,76.14) v1(90.87,75.06) v1(90.93,72.14) v1(91.12,66.61) v1(91.44,70.74) v1(91.5,57.09) v1(91.82,120.78) v1(91.76,80.77) v1(91.88,93.85) v1(91.88,87.38) v1(91.95,68.07) v1(92.33,99.38) v1(92.52,73.72) v1(92.71,78.42) v1(92.71,64.45) v1(92.77,77.03) v1(92.77,72.2) v1(93.09,69.28) v1(93.85,120.78) v1(93.92,110.11) v1(94.42,104.01) v1(94.49,96.52) v1(94.49,94.87) v1(94.49,75.69) v1(94.81,70.74) v1(94.93,68.07) v1(95.31,79.95) v1(95.31,66.61) v1(95.5,120.78) v1(95.69,86.04) v1(95.71,83.39) v1(96.08,77.34) v1(96.27,103.12) v1(96.27,100.33) v1(96.33,89.09) v1(96.27,88.27) v1(96.39,96.77) v1(96.65,101.22) v1(96.65,94.74) v1(96.65,93.28) v1(96.65,64.45) v1(96.8,105.77) v1(97.03,120.78) v1(97.03,72.2) v1(97.13,84.05) v1(97.09,69.34) v1(97.79,80.01) v1(97.79,78.74) v1(97.85,77.22) v1(98.07,106.43) v1(98.11,104.46) v1(98.12,85.62) v1(98.12,84.94) v1(98.17,60.2) v1(98.49,68.14) v1(98.55,110.36) v1(98.65,89.31) v1(99.24,105.71) v1(99.19,95.69) v1(99.31,120.78) v1(99.31,70.8) v1(99.82,110.36) v1(99.82,64.45) v1(99.95,104.46) v1(99.89,102.68) v1(100.08,66.61) v1(100.58,93.22) v1(100.58,92.52) v1(100.74,95.17) v1(100.97,120.78) v1(100.97,88.67) v1(101.16,103.31) v1(101.32,105.77) v1(101.28,93.22) v1(101.28,92.52) v1(101.41,72.2) v1(101.54,76.96) v1(101.54,69.41) v1(102.43,68.07) v1(102.49,120.78) v1(102.49,104.52) v1(102.49,101.98) v1(102.87,91.31) v1(102.93,66.61) v1(103.03,59.85) v1(103.31,80.14) v1(103.25,70.8) v1(103.89,103.25) v1(103.96,105.82) v1(104.52,120.78) v1(104.52,110.49) v1(104.65,112.27) v1(104.73,74.25) v1(104.71,64.58) v1(105.16,72.2) v1(105.16,66.61) v1(105.28,101.98) v1(105.6,106.43) v1(105.73,68.14) v1(105.92,112.27) v1(106.17,120.78) v1(106.3,103.25) v1(106.55,99.82) v1(106.81,66.61) v1(107.44,104.01) v1(107.44,70.74) v1(107.44,69.34) v1(107.51,72.2) v1(107.7,120.78) v1(107.7,112.39) v1(107.7,110.87) v1(107.7,105.66) v1(107.82,98.68) v1(107.81,14.45) v1(108.48,106.71) v1(108.97,112.65) v1(108.97,110.87) v1(108.97,99.31) v1(109.09,104.39) v1(109.3,84) v1(109.86,69.34) v1(110.11,103.25) v1(110.24,120.78) v1(110.24,64.52) v1(110.24,61.34) v1(110.3,66.61) v1(110.43,101.03) v1(110.49,104.78) v1(110.55,98.62) v1(110.62,75.44) v1(110.74,112.14) v1(110.69,106.5) v1(110.74,68.45) v1(111.51,69.41) v1(111.57,66.61) v1(111.57,64.45) v1(111.82,98.74) v1(111.89,120.78) v1(111.89,103.38) v1(112.14,112.14) v1(112.17,95.83) v1(112.27,100.9) v1(112.52,106.43) v1(112.52,104.65) v1(112.97,70.74) v1(113.22,62.36) v1(113.41,120.78) v1(113.41,82.8) v1(113.54,64.58) v1(113.6,66.61) v1(113.79,112.01) v1(113.79,110.74) v1(113.79,103.38) v1(114.3,104.65) v1(114.81,82.61) v1(115.13,66.61) v1(115.19,112.14) v1(115.19,110.62) v1(115.21,91.08) v1(115.19,64.58) v1(115.19,55.12) v1(115.34,53.42) v1(115.53,89.94) v1(115.57,120.78) v1(115.7,56.39) v1(115.78,91.78) v1(116.04,88.98) v1(116.2,103.89) v1(116.23,90.7) v1(116.59,99.39) v1(116.59,82.23) v1(116.65,75.95) v1(116.73,88.16) v1(116.71,74.96) v1(116.84,80.2) v1(116.93,91.59) v1(116.86,89.75) v1(116.87,78.28) v1(117.03,53.28) v1(117.09,55.18) v1(117.22,120.78) v1(117.22,66.61) v1(117.35,62.36) v1(117.41,64.52) v1(117.5,88.98) v1(117.56,90.51) v1(117.79,56.39) v1(117.92,101.41) v1(117.91,99.39) v1(117.98,103.5) v1(118.13,88.22) v1(118.2,91.59) v1(118.26,89.56) v1(118.29,79.58) v1(118.39,76.1) v1(118.36,74.93) v1(118.62,112.27) v1(118.62,78.23) v1(118.75,120.78) v1(118.83,88.98) v1(118.87,107.95) v1(118.89,90.7) v1(118.92,71.55) v1(119.13,67.82) v1(119.23,99.44) v1(119.19,69.66) v1(119.19,66.61) v1(119.19,62.36) v1(119.25,64.52) v1(119.38,103.38) v1(119.53,89.94) v1(120.12,97.54) v1(120.14,72.64) v1(120.27,80.52) v1(120.4,101.35) v1(120.46,74.17) v1(120.65,120.78) v1(120.78,104.65) v1(121.21,77.04) v1(121.28,87.45) v1(121.28,80.52) v1(121.54,68.26) v1(121.92,105.74) v1(122.17,103.25) v1(122.2,75.92) v1(122.3,120.78) v1(122.3,80.52) v1(122.43,101.22) v1(123.19,80.52) v1(123.34,75.92) v1(123.83,120.78) v1(123.89,81.41) v1(124.1,105.71) v1(124.36,89.43) v1(124.59,100.46) v1(124.8,91.52) v1(124.78,81.41) v1(124.97,103.38) v1(125.6,120.78) v1(125.86,98.93) v1(125.86,81.09) v1(126.11,107.06) v1(126.07,85.75) v1(126.36,102.23) v1(126.75,81.09) v1(127.02,85.68) v1(127.25,120.78) v1(127.46,105.79) v1(127.51,82.11) v1(127.64,100.71) v1(128.21,36.89) v1(128.21,35.56) v1(128.21,34.16) v1(128.27,38.23) v1(128.65,104.39) v1(128.78,120.78) v1(129.41,32.32) v1(130.43,106.55) v1(130.81,120.78) v1(131.32,85.47) v1(131.44,104.65) v1(132.36,45.16) v1(132.46,120.78) v1(132.84,85.47) v1(133.31,89.62) v1(133.48,106.81) v1(133.88,45.16) v1(133.99,120.78) v1(133.96,32.64) v1(134.26,85.56) v1(134.77,89.68) v1(135.02,88.29) v1(135.48,45.16) v1(136.02,120.78) v1(137.13,43.89) v1(137.67,120.78) v1(137.79,37.82) v1(138.23,38.21) v1(138.33,43.1) v1(138.74,38.59) v1(138.74,37.82) v1(139.19,120.78) v2(0.76,151.89) v2(0.76,148.97) v2(0.76,146.05) v2(0.76,143.13) v2(0.76,140.46) v2(0.76,137.54) v2(0.76,134.87) v2(0.76,131.95) v2(0.76,129.29) v2(0.76,126.36) v2(0.76,123.44) v2(0.76,120.52) v2(0.76,117.86) v2(0.76,114.94) v2(0.76,112.27) v2(0.76,109.35) v2(0.76,106.68) v2(0.76,103.76) v2(0.76,100.84) v2(0.76,97.92) v2(0.76,95.25) v2(0.76,92.33) v2(0.76,89.66) v2(0.76,86.74) v2(0.76,84.07) v2(0.76,81.15) v2(0.76,78.23) v2(0.76,75.31) v2(0.76,72.64) v2(0.76,69.72) v2(0.76,67.06) v2(0.76,64.14) v2(0.76,61.47) v2(0.76,58.55) v2(0.76,55.88) v2(0.76,52.96) v2(0.76,50.29) v2(0.76,47.37) v2(0.76,44.7) v2(0.76,41.78) v2(0.76,39.12) v2(0.76,36.2) v2(0.76,33.53) v2(0.76,30.61) v2(0.76,27.94) v2(0.76,25.02) v2(0.76,22.35) v2(0.76,19.81) v2(1.02,17.27) v2(1.52,154.43) v2(1.78,14.22) v2(2.29,157.23) v2(2.79,11.43) v2(3.56,160.02) v2(3.81,144.78) v2(3.81,67.31) v2(3.81,62.23) v2(3.81,57.15) v2(3.81,48.26) v2(3.81,43.18) v2(3.81,38.1) v2(3.81,33.02) v2(3.81,27.94) v2(3.81,22.86) v2(4.13,135.83) v2(4.13,130.49) v2(4.13,124.84) v2(4.13,119.44) v2(4.19,91.31) v2(4.32,8.89) v2(4.45,111.44) v2(5.02,113.28) v2(5.21,81.92) v2(5.21,78.61) v2(5.33,162.31) v2(5.33,89.41) v2(5.33,85.47) v2(5.71,157.48) v2(6.1,6.6) v2(6.35,139.38) v2(6.35,50.8) v2(6.35,45.72) v2(6.35,40.64) v2(6.35,35.56) v2(6.35,30.48) v2(6.35,25.4) v2(7.37,164.59) v2(8.13,5.08) v2(8.26,160.02) v2(8.89,48.26) v2(8.89,43.18) v2(8.89,38.1) v2(8.89,33.02) v2(8.89,27.94) v2(8.89,22.86) v2(9.02,140.65) v2(9.65,166.12) v2(9.84,50.99) v2(10.67,3.3) v2(10.79,162.56) v2(10.79,157.48) v2(11.43,45.72) v2(11.43,40.64) v2(11.43,35.56) v2(11.43,30.48) v2(11.43,25.4) v2(11.43,20.32) v2(12.06,140.59) v2(12.19,167.64) v2(13.21,50.86) v2(13.34,165.1) v2(13.34,160.02) v2(13.34,154.94) v2(13.46,2.03) v2(13.97,145.41) v2(13.97,48.26) v2(13.97,43.18) v2(13.97,38.1) v2(13.97,33.02) v2(13.97,27.94) v2(13.97,22.86) v2(13.97,17.78) v2(13.97,12.7) v2(13.97,7.62) v2(14.35,152.34) v2(14.73,168.4) v2(14.67,57.09) v2(14.67,55.75) v2(14.67,54.48) v2(14.67,53.28) v2(15.24,77.85) v2(15.24,63.5) v2(15.24,59.69) v2(15.68,159.38) v2(15.68,157.99) v2(15.68,156.72) v2(15.75,140.46) v2(15.88,162.56) v2(16.26,1.27) v2(16.51,45.72) v2(16.51,40.64) v2(16.51,35.56) v2(16.51,30.48) v2(16.51,25.4) v2(16.51,20.32) v2(16.51,15.24) v2(16.51,10.16) v2(16.51,5.08) v2(17.72,169.16) v2(17.84,165.42) v2(17.84,154.88) v2(17.91,161.73) v2(18.99,50.86) v2(18.99,46.04) v2(19.05,48.51) v2(19.05,47.37) v2(19.05,43.18) v2(19.05,38.1) v2(19.05,33.02) v2(19.05,27.94) v2(19.05,22.86) v2(19.05,17.78) v2(19.05,12.7) v2(19.05,7.62) v2(19.05,2.54) v2(19.05,0.76) v2(19.88,140.4) v2(20.32,145.73) v2(20.32,44.64) v2(21.53,44.64) v2(21.59,40.64) v2(21.59,35.56) v2(21.59,30.48) v2(21.59,25.4) v2(21.59,20.32) v2(21.59,15.24) v2(21.59,10.16) v2(21.59,5.08) v2(21.59,0.76) v2(21.84,154.88) v2(21.84,142.18) v2(22.42,145.73) v2(22.67,140.46) v2(22.73,77.85) v2(22.73,44.64) v2(23.24,144.53) v2(23.62,48.64) v2(23.56,47.18) v2(23.56,45.85) v2(23.81,50.74) v2(24.13,67.31) v2(24.13,66.17) v2(24.13,63.5) v2(24.13,43.18) v2(24.13,38.1) v2(24.13,33.02) v2(24.13,27.94) v2(24.13,22.86) v2(24.13,17.78) v2(24.13,12.7) v2(24.13,7.62) v2(24.13,2.54) v2(24.38,0.76) v2(25.02,72.01) v2(25.02,70.87) v2(25.02,69.72) v2(25.02,68.58) v2(25.02,67.31) v2(25.02,66.17) v2(25.34,154.81) v2(25.59,144.59) v2(26.04,140.46) v2(26.61,146.49) v2(26.67,40.64) v2(26.67,35.56) v2(26.67,30.48) v2(26.67,25.4) v2(26.67,20.32) v2(26.67,15.24) v2(26.67,10.16) v2(26.67,5.08) v2(26.8,71.88) v2(26.8,70.61) v2(27.05,77.85) v2(27.18,0.76) v2(27.62,142.75) v2(27.69,69.85) v2(27.81,144.53) v2(28.64,140.65) v2(29.08,143.76) v2(29.21,43.18) v2(29.21,38.1) v2(29.21,33.02) v2(29.21,27.94) v2(29.21,22.86) v2(29.21,17.78) v2(29.21,12.7) v2(29.21,7.62) v2(29.21,2.54) v2(29.27,148.78) v2(29.84,76.33) v2(29.84,75.44) v2(29.97,0.76) v2(30.48,73.66) v2(30.86,76.33) v2(30.86,75.44) v2(31.11,69.72) v2(31.11,68.83) v2(31.75,40.64) v2(31.75,35.56) v2(31.75,25.4) v2(31.75,20.32) v2(31.75,10.16) v2(31.75,5.08) v2(32.13,69.72) v2(32.13,68.83) v2(32.51,77.22) v2(32.51,46.1) v2(32.51,0.76) v2(32.64,88.27) v2(32.64,84.58) v2(32.64,82.04) v2(32.64,79.63) v2(32.58,50.42) v2(32.58,48.58) v2(32.58,47.43) v2(33.32,86.92) v2(33.85,51.94) v2(33.85,44.7) v2(33.98,85.31) v2(34.16,81.53) v2(34.29,72.39) v2(34.29,66.04) v2(34.29,33.02) v2(34.29,27.94) v2(34.29,22.86) v2(34.29,7.62) v2(34.29,2.54) v2(35.05,79.5) v2(35.05,78.3) v2(35.05,75.37) v2(35.05,74.36) v2(35.05,44.7) v2(35.31,0.76) v2(35.81,51.94) v2(36.26,44.7) v2(36.83,40.64) v2(36.83,35.56) v2(36.83,30.48) v2(36.83,25.4) v2(36.83,20.32) v2(36.83,5.08) v2(36.96,80.64) v2(37.15,50.67) v2(37.15,48.7) v2(37.08,47.24) v2(37.08,45.91) v2(37.79,87.18) v2(38.1,0.76) v2(38.48,83.57) v2(39,87.13) v2(39.37,53.34) v2(39.37,48.26) v2(39.37,43.18) v2(39.37,38.1) v2(39.37,33.02) v2(39.37,22.86) v2(39.37,19.05) v2(39.37,7.62) v2(39.37,2.54) v2(40.01,76.9) v2(40.32,169.23) v2(40.32,165.42) v2(40.26,161.8) v2(40.32,154.56) v2(40.26,76.14) v2(40.77,76.9) v2(40.89,0.76) v2(40.96,156.91) v2(41.08,76.14) v2(41.27,88.52) v2(41.4,78.11) v2(41.53,149.29) v2(41.47,77.34) v2(41.59,76.64) v2(41.91,55.88) v2(41.91,50.8) v2(41.91,45.72) v2(41.91,40.64) v2(41.91,35.56) v2(41.91,20.32) v2(41.91,5.08) v2(42.1,159.32) v2(42.1,158.05) v2(42.55,71.63) v2(42.55,70.36) v2(42.55,68.83) v2(42.55,67.44) v2(42.61,74.17) v2(42.61,72.96) v2(42.61,66.1) v2(43.18,169.29) v2(43.69,0.76) v2(44.01,151.96) v2(44.45,58.42) v2(44.45,53.34) v2(44.45,48.26) v2(44.45,43.18) v2(44.45,7.62) v2(44.45,2.54) v2(44.7,74.3) v2(44.83,77.47) v2(44.83,76.33) v2(44.96,73.03) v2(45.15,160.53) v2(45.53,153.48) v2(45.72,67.31) v2(46.23,169.29) v2(46.48,88.65) v2(46.48,0.76) v2(46.61,152.08) v2(46.67,162.18) v2(46.99,60.96) v2(46.99,55.88) v2(46.99,50.8) v2(47.43,149.61) v2(47.62,19.05) v2(48.13,64.58) v2(48.26,72.07) v2(48.26,68.26) v2(48.39,158.69) v2(48.39,157.67) v2(48.77,166.24) v2(49.28,0.76) v2(49.53,7.62) v2(49.72,169.29) v2(49.66,71.88) v2(49.66,64.45) v2(50.04,9.65) v2(50.36,149.67) v2(50.42,6.35) v2(50.8,85.85) v2(50.99,68.33) v2(50.99,64.58) v2(51.05,80.9) v2(51.05,72.07) v2(52.07,0.76) v2(52.2,88.52) v2(53.47,3.3) v2(53.66,164.08) v2(53.72,5.97) v2(54.04,169.29) v2(53.98,165.35) v2(54.61,0.76) v2(54.86,162.5) v2(54.86,159.7) v2(54.86,156.21) v2(54.86,152.78) v2(55.05,166.81) v2(55.88,67.69) v2(56.26,149.03) v2(56.39,83.95) v2(56.52,19.05) v2(57.15,7.49) v2(57.4,89.41) v2(57.4,0.76) v2(58.67,146.56) v2(59.18,5.71) v2(59.82,91.82) v2(60.2,101.35) v2(60.2,0.76) v2(60.33,126.11) v2(60.33,120.27) v2(60.33,115.95) v2(60.33,111.63) v2(60.33,106.17) v2(60.33,96.9) v2(60.45,79.76) v2(60.58,85.85) v2(60.96,5.71) v2(61.09,10.03) v2(61.59,84.33) v2(61.72,87.12) v2(62.99,6.6) v2(62.99,0.76) v2(63.25,68.2) v2(64.14,3.81) v2(64.64,103.89) v2(65.66,69.72) v2(65.79,0.76) v2(66.04,9.78) v2(66.42,67.06) v2(66.55,6.1) v2(68.33,112.01) v2(68.33,110.87) v2(68.33,109.73) v2(68.58,28.57) v2(68.58,21.59) v2(68.58,0.76) v2(69.47,80.52) v2(71.37,9.65) v2(71.37,0.76) v2(72.01,6.6) v2(72.77,80.39) v2(73.03,112.71) v2(73.28,109.86) v2(73.66,33.02) v2(73.66,27.94) v2(73.66,22.86) v2(73.66,17.78) v2(73.91,4.32) v2(74.17,0.76) v2(75.18,70.99) v2(76.2,35.56) v2(76.2,30.48) v2(76.2,25.4) v2(76.2,20.32) v2(76.45,9.78) v2(76.45,6.73) v2(76.71,0.76) v2(76.9,112.78) v2(77.34,109.98) v2(78.74,38.1) v2(78.74,33.02) v2(78.74,27.94) v2(78.74,22.86) v2(78.74,17.78) v2(78.87,70.99) v2(78.99,6.22) v2(79.5,0.76) v2(80.9,5.84) v2(82.3,9.27) v2(82.3,0.76) v2(82.42,112.65) v2(82.55,108.46) v2(82.8,14.48) v2(83.19,106.81) v2(83.31,75.31) v2(83.82,3.17) v2(84.07,5.97) v2(85.04,113.39) v2(85.09,0.76) v2(85.85,9.4) v2(86.41,112.32) v2(87,107.82) v2(87.63,0.76) v2(88.9,5.84) v2(90.42,0.76) v2(90.55,106.55) v2(90.68,110.62) v2(91.69,2.54) v2(92.58,6.6) v2(93.22,0.76) v2(95.38,110.74) v2(95.5,9.27) v2(96.01,0.76) v2(96.52,74.1) v2(96.9,110.74) v2(97.79,6.1) v2(98.55,0.76) v2(99.95,2.41) v2(101.22,5.84) v2(101.35,0.76) v2(101.47,110.74) v2(102.87,8.89) v2(102.87,3.81) v2(103,110.74) v2(104.14,0.76) v2(105.41,6.35) v2(106.17,110.11) v2(106.93,0.76) v2(107.95,8.89) v2(107.95,3.81) v2(109.73,0.76) v2(110.49,6.35) v2(110.62,110.11) v2(112.14,110.11) v2(112.52,0.76) v2(113.03,8.89) v2(113.03,3.81) v2(114.33,74.17) v2(115.32,0.76) v2(115.57,6.35) v2(118.11,8.89) v2(118.11,3.81) v2(118.11,0.76) v2(120.65,6.35) v2(120.65,0.76) v2(121.28,110.24) v2(122.17,72.01) v2(123.11,98.86) v2(123.22,95.25) v2(123.19,8.89) v2(123.19,3.81) v2(123.25,45.85) v2(123.44,0.76) v2(124.18,97.33) v2(124.21,96.47) v2(124.21,62.46) v2(124.27,50.04) v2(124.46,64.39) v2(125.09,110.24) v2(125.48,44.77) v2(125.6,51.24) v2(125.73,6.35) v2(126.24,64.39) v2(126.24,0.76) v2(126.36,41.72) v2(127,63.56) v2(127.19,44.77) v2(128.33,40.96) v2(128.27,8.89) v2(128.27,3.81) v2(128.65,57.98) v2(128.84,47.82) v2(128.78,45.85) v2(128.78,42.93) v2(128.91,110.24) v2(129.03,0.76) v2(129.41,70.48) v2(129.54,102.87) v2(129.54,97.79) v2(130.3,65.28) v2(130.75,57.66) v2(130.81,6.35) v2(131.57,1.02) v2(131.95,82.3) v2(131.95,63.44) v2(132.08,100.33) v2(132.33,65.28) v2(132.72,110.24) v2(133.1,47.75) v2(133.35,8.89) v2(133.35,3.81) v2(133.6,76.33) v2(134.43,67.44) v2(134.43,66.67) v2(134.37,1.27) v2(134.62,102.87) v2(134.62,97.79) v2(134.81,63.75) v2(134.94,66.17) v2(135.19,67.63) v2(135.19,66.93) v2(135.64,152.27) v2(135.64,66.17) v2(135.76,158.12) v2(135.76,155.57) v2(135.83,63.94) v2(135.89,31.75) v2(135.89,11.43) v2(135.89,6.35) v2(136.14,165.99) v2(136.14,161.93) v2(136.33,66.29) v2(136.4,167.89) v2(136.53,72.64) v2(136.58,105.51) v2(136.65,57.02) v2(137.03,45.72) v2(137.16,110.49) v2(137.16,80.01) v2(137.16,24.13) v2(137.29,53.09) v2(137.41,2.54) v2(137.73,72.64) v2(137.99,35.24) v2(138.18,167.13) v2(138.43,8.89) v2(138.43,3.81) v2(138.56,155.07) v2(139.06,160.66) v2(139.7,118.11) v2(139.7,113.03) v2(139.7,107.95) v2(139.7,102.87) v2(139.7,97.79) v2(139.7,87.63) v2(139.7,82.55) v2(139.7,77.47) v2(139.7,31.75) v2(139.7,21.59) v2(139.95,3.81) v2(140.21,166.12) v2(140.59,162.81) v2(140.84,37.15) v2(140.97,6.35) v2(141.67,120.65) v2(141.99,37.15) v2(142.11,143.38) v2(142.24,164.59) v2(142.24,115.57) v2(142.24,110.49) v2(142.24,105.41) v2(142.24,100.33) v2(142.24,80.01) v2(142.24,74.93) v2(142.24,69.85) v2(142.24,29.21) v2(142.24,24.13) v2(142.24,5.59) v2(142.37,156.46) v2(142.88,35.12) v2(143,45.47) v2(143.23,40.45) v2(143.23,39.69) v2(143.51,8.89) v2(144.02,58.67) v2(144.27,162.56) v2(144.27,158.24) v2(144.27,7.37) v2(144.78,140.08) v2(144.78,118.11) v2(144.78,113.03) v2(144.78,107.95) v2(144.78,102.87) v2(144.78,97.79) v2(144.78,92.71) v2(144.78,87.63) v2(144.78,82.55) v2(144.78,77.47) v2(144.78,72.39) v2(144.78,57.15) v2(144.78,52.07) v2(144.78,31.75) v2(144.78,26.67) v2(144.78,21.59) v2(145.03,39.24) v2(146.05,160.53) v2(146.05,154.43) v2(146.05,9.65) v2(146.56,144.78) v2(146.69,136.53) v2(146.69,132.21) v2(146.69,127.89) v2(146.69,123.32) v2(147.32,157.99) v2(147.32,115.57) v2(147.32,110.49) v2(147.32,105.41) v2(147.32,100.33) v2(147.32,95.25) v2(147.32,90.17) v2(147.32,85.09) v2(147.32,80.01) v2(147.32,74.93) v2(147.32,69.85) v2(147.32,64.77) v2(147.32,59.69) v2(147.32,54.61) v2(147.32,49.53) v2(147.32,44.45) v2(147.32,24.13) v2(147.32,11.94) v2(148.34,155.45) v2(148.34,14.99) v2(148.84,17.53) v2(149.1,152.4) v2(149.1,149.1) v2(149.1,146.3) v2(149.1,143.38) v2(149.1,140.72) v2(149.1,137.79) v2(149.1,135.13) v2(149.1,132.21) v2(149.1,129.54) v2(149.1,126.62) v2(149.1,123.7) v2(149.1,120.78) v2(149.1,118.11) v2(149.1,115.19) v2(149.1,112.52) v2(149.1,109.6) v2(149.1,106.93) v2(149.1,104.01) v2(149.1,101.09) v2(149.1,98.17) v2(149.1,95.5) v2(149.1,92.58) v2(149.1,89.92) v2(149.1,87) v2(149.1,84.33) v2(149.1,81.41) v2(149.1,78.49) v2(149.1,75.56) v2(149.1,72.9) v2(149.1,69.98) v2(149.1,67.31) v2(149.1,64.39) v2(149.1,61.72) v2(149.1,58.8) v2(149.1,56.13) v2(149.1,53.21) v2(149.1,50.55) v2(149.1,47.62) v2(149.1,44.96) v2(149.1,42.04) v2(149.1,39.37) v2(149.1,36.45) v2(149.1,33.78) v2(149.1,30.86) v2(149.1,28.19) v2(149.1,25.27) v2(149.1,22.61) v2(149.1,20.07) v3(71.31,112) v3(71.31,110.88) v3(72.52,103.94) v3(72.52,102.82) v3(72.68,112) v3(72.68,110.88) v3(73.89,103.94) v3(73.89,102.82) v3(74.96,103.89) v3(74.96,102.77) v3(75.16,112.62) v3(75.31,110.88) v3(76.33,103.89) v3(76.33,102.77) v3(76.68,112) v3(76.68,110.88) v3(76.91,104.83) v3(76.91,103.71) v3(77.09,84.23) v3(77.09,83.11) v3(78.28,104.83) v3(78.28,103.71) v3(78.46,84.23) v3(78.46,83.11) v3(78.97,104.9) v3(78.97,103.78) v3(79.32,111.96) v3(79.32,110.85) v3(79.4,84.2) v3(79.4,83.08) v3(80.34,104.9) v3(80.34,103.78) v3(80.7,111.96) v3(80.7,110.85) v3(80.77,84.2) v3(80.77,83.08) v3(83.21,111.56) v3(83.51,110.85) v3(84.89,112.01) v3(84.89,110.85) v3(93.07,108.97) v3(93.07,107.85) v3(94.44,108.97) v3(94.61,107.95) v3(95.45,108.71) v3(95.45,107.59) v3(96.83,108.71) v3(96.83,107.59) v3(98.48,108.92) v3(98.48,107.8) v3(99.85,108.92) v3(99.85,107.8) v3(101.55,108.79) v3(101.55,107.67) v3(102.92,108.79) v3(102.92,107.67) v3(104.65,108.84) v3(104.65,107.72) v3(106.02,108.84) v3(106.02,107.72) v3(107.64,109.02) v3(107.64,107.9) v3(109.02,109.02) v3(109.14,107.9) v3(110.26,72.16) v3(110.26,70.79) v3(110.77,109.3) v3(110.77,108.18) v3(111.38,72.16) v3(111.38,70.79) v3(112.14,109.3) v3(112.14,108.18) v3(113.74,108.99) v3(113.74,107.87) v3(113.72,69.27) v3(113.72,68.15) v3(115.11,108.99) v3(115.11,107.87) v3(115.09,69.27) v3(115.09,68.15) v3(115.85,70.03) v3(115.85,68.91) v3(116.86,73.74) v3(116.86,72.62) v3(117.22,70.03) v3(117.22,68.91) v3(118.24,73.74) v3(118.24,72.62) v3(122.5,110.52) v3(122.5,109.4) v3(123.88,110.52) v3(123.88,109.4) v3(126.36,110.54) v3(126.36,109.42) v3(127.74,110.54) v3(127.74,109.42) v3(130.25,110.54) v3(130.25,109.42) v3(131.62,110.54) v3(131.62,109.42) v3(134.11,110.54) v3(134.11,109.42) v3(135.48,110.54) v3(135.48,109.42) v4(35.56,30.48) v4(40.01,27.3) v4(41.91,26.04) v4(41.91,24.77) v4(41.91,23.5) v4(43.12,22.35) v4(43.18,33.02) v4(43.18,28.57) v4(46.02,26.88) v4(47.05,39.31) v4(47.9,28.76) v4(48.59,27.29) v4(49.47,34.73) v4(49.56,27.07) v4(49.61,24.29) v4(49.91,39.62) v4(50.25,28.1) v4(53.09,39.94) v4(53.4,34.04) v4(53.79,29.84) v4(53.8,28.25) v4(54.74,37.27) v4(55.96,27.23) v4(56.95,26.45) v4(57.15,31.52) v4(57.66,28.7) v4(57.86,30.04) v4(59.03,30.75) v4(59.51,31.56) v4(61.19,31.14) v4(61.16,27.53) v4(62.1,27.91) v4(63.4,22.99) v4(63.7,29.02) v4(72.83,46.42) v4(72.83,42.04) v4(73.47,50.23) v4(75.87,41.43) v4(75.97,39.22) v4(76.91,40.89) v4(82.25,47.52) v4(82.63,48.74) v4(84.39,49.85) v4(85.7,44.48) v4(85.79,49.91) v4(86.04,46.29) v4(86.74,50.86) v4(87.69,51.69) v4(87.69,45.97) v4(90.42,53.02) v4(91.82,53.02) v4(113.5,11.57) v4(115,10.67) v4(125.73,11.43) v4(128.33,28.13) v4(128.27,13.97) v4(128.46,25.84) v4(129.54,29.65) v4(130.37,26.16) v4(130.81,16.51) v4(130.81,11.43) v4(132.21,26.16) v4(133.29,22.67) v4(133.29,21.59) v4(134.81,25.27) v4(134.81,22.73) v4(134.81,21.91) v4(135.89,17.78) v4(138.56,26.48) v4(138.56,25.65)
